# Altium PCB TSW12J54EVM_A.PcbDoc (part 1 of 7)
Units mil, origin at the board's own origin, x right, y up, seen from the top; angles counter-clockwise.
Board outline 6301 x 2680 mil, 10 copper layers (Top Layer - L1, Gnd-Plane - L2, Signals - L3, Gnd-Plane - L4, Pwr Plane - L5, Signals - L6, Gnd-Plane - L7, Signals - L8, Gnd-Plane - L9, Bottom Layer - L10), stack 57.8 mil thick; 650 components, 374 nets, 2074 pads, 1402 vias.
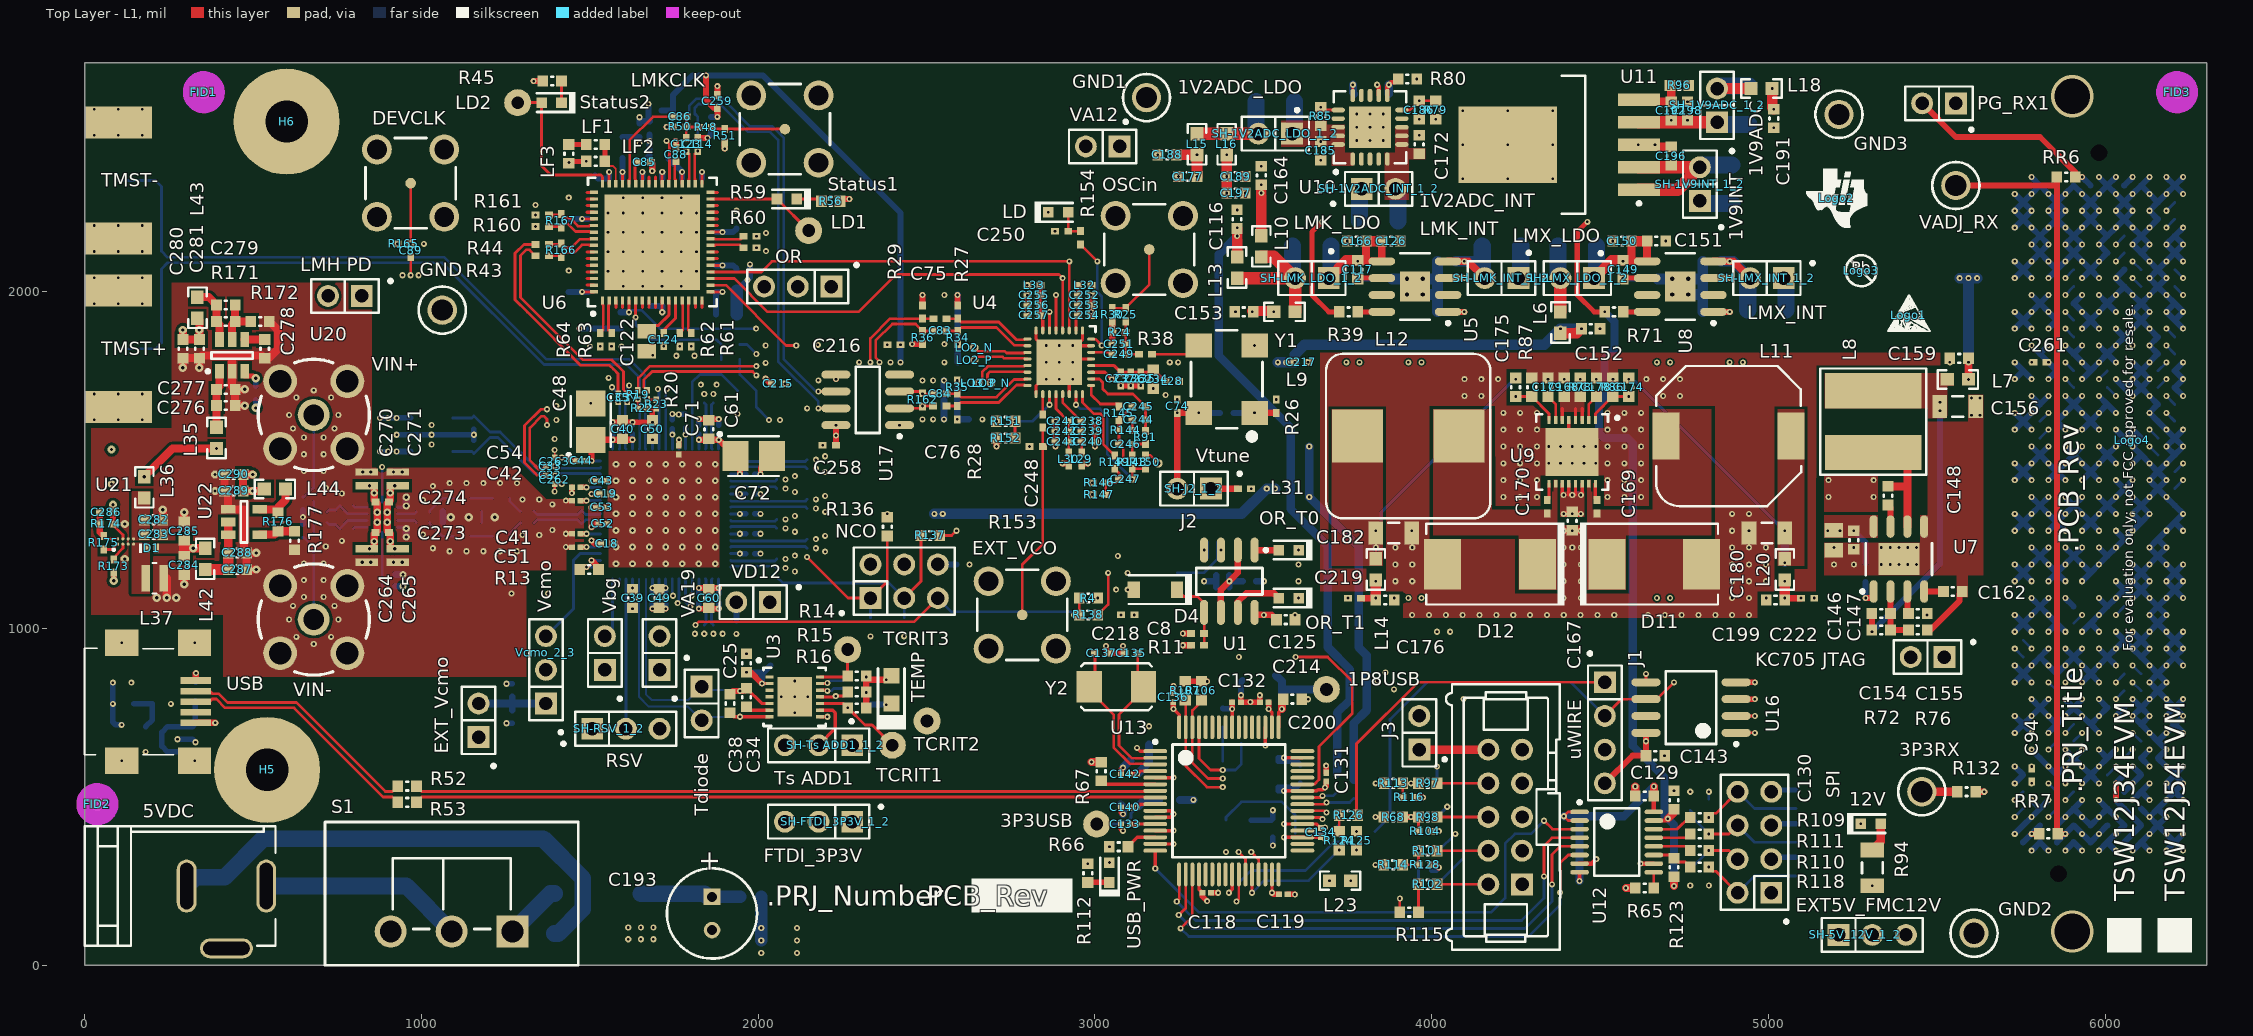
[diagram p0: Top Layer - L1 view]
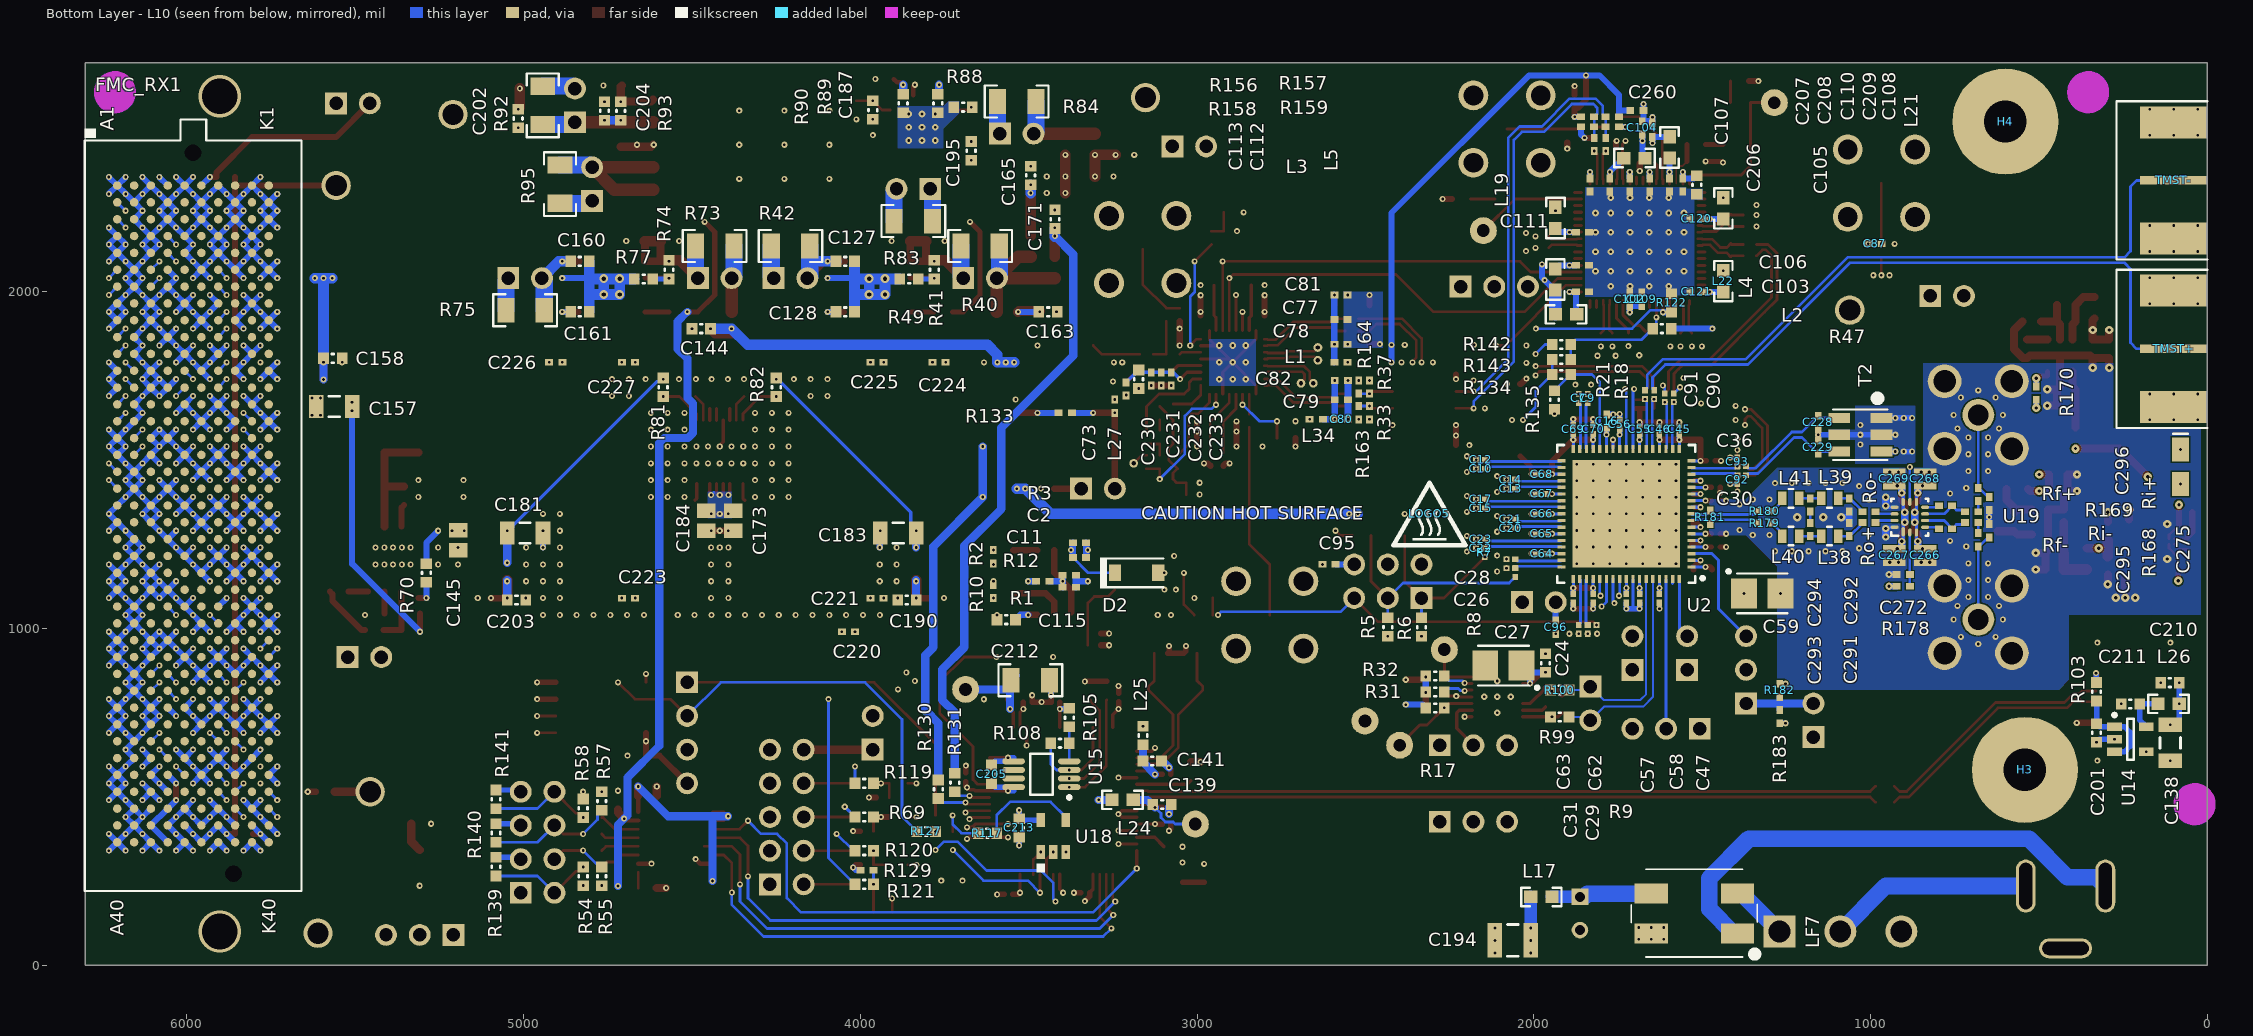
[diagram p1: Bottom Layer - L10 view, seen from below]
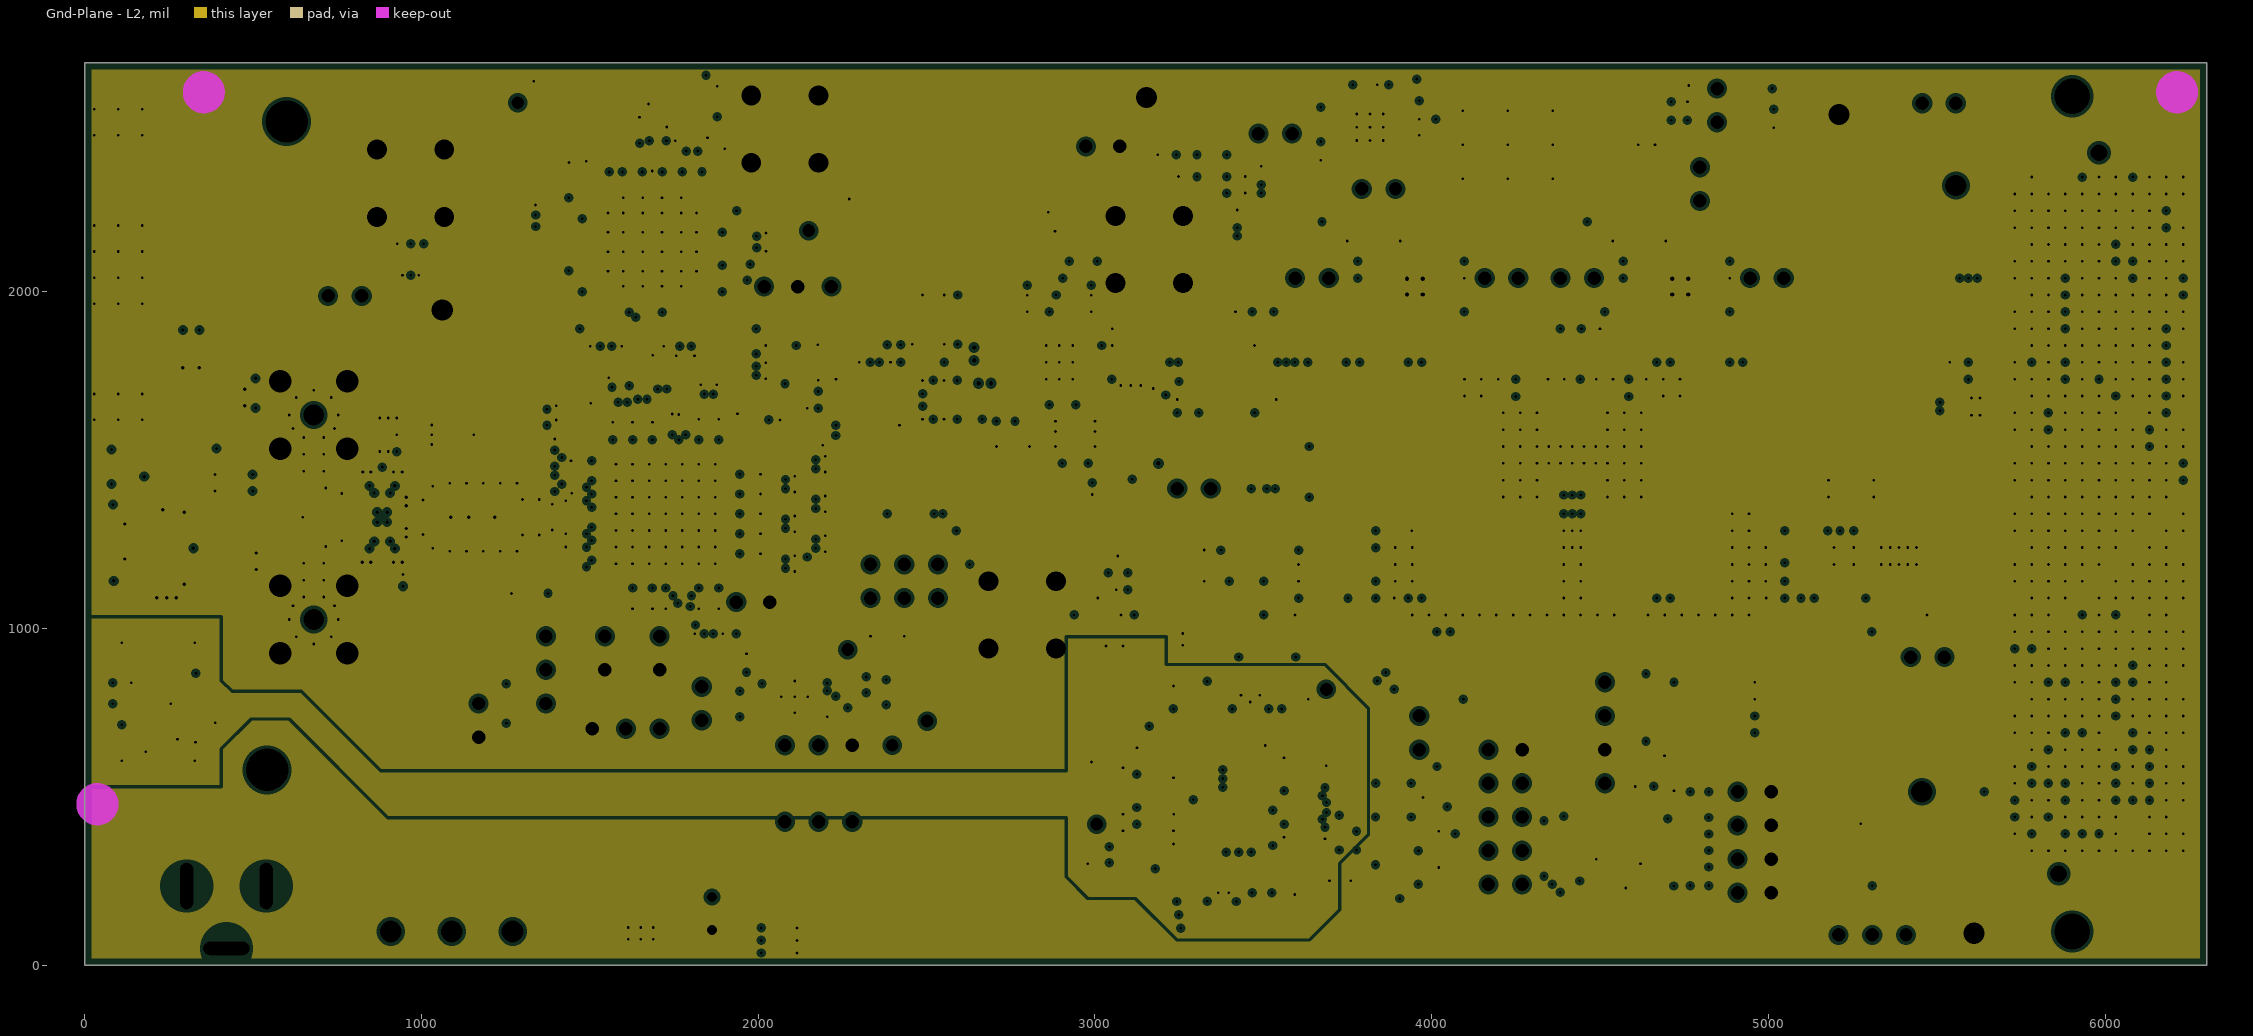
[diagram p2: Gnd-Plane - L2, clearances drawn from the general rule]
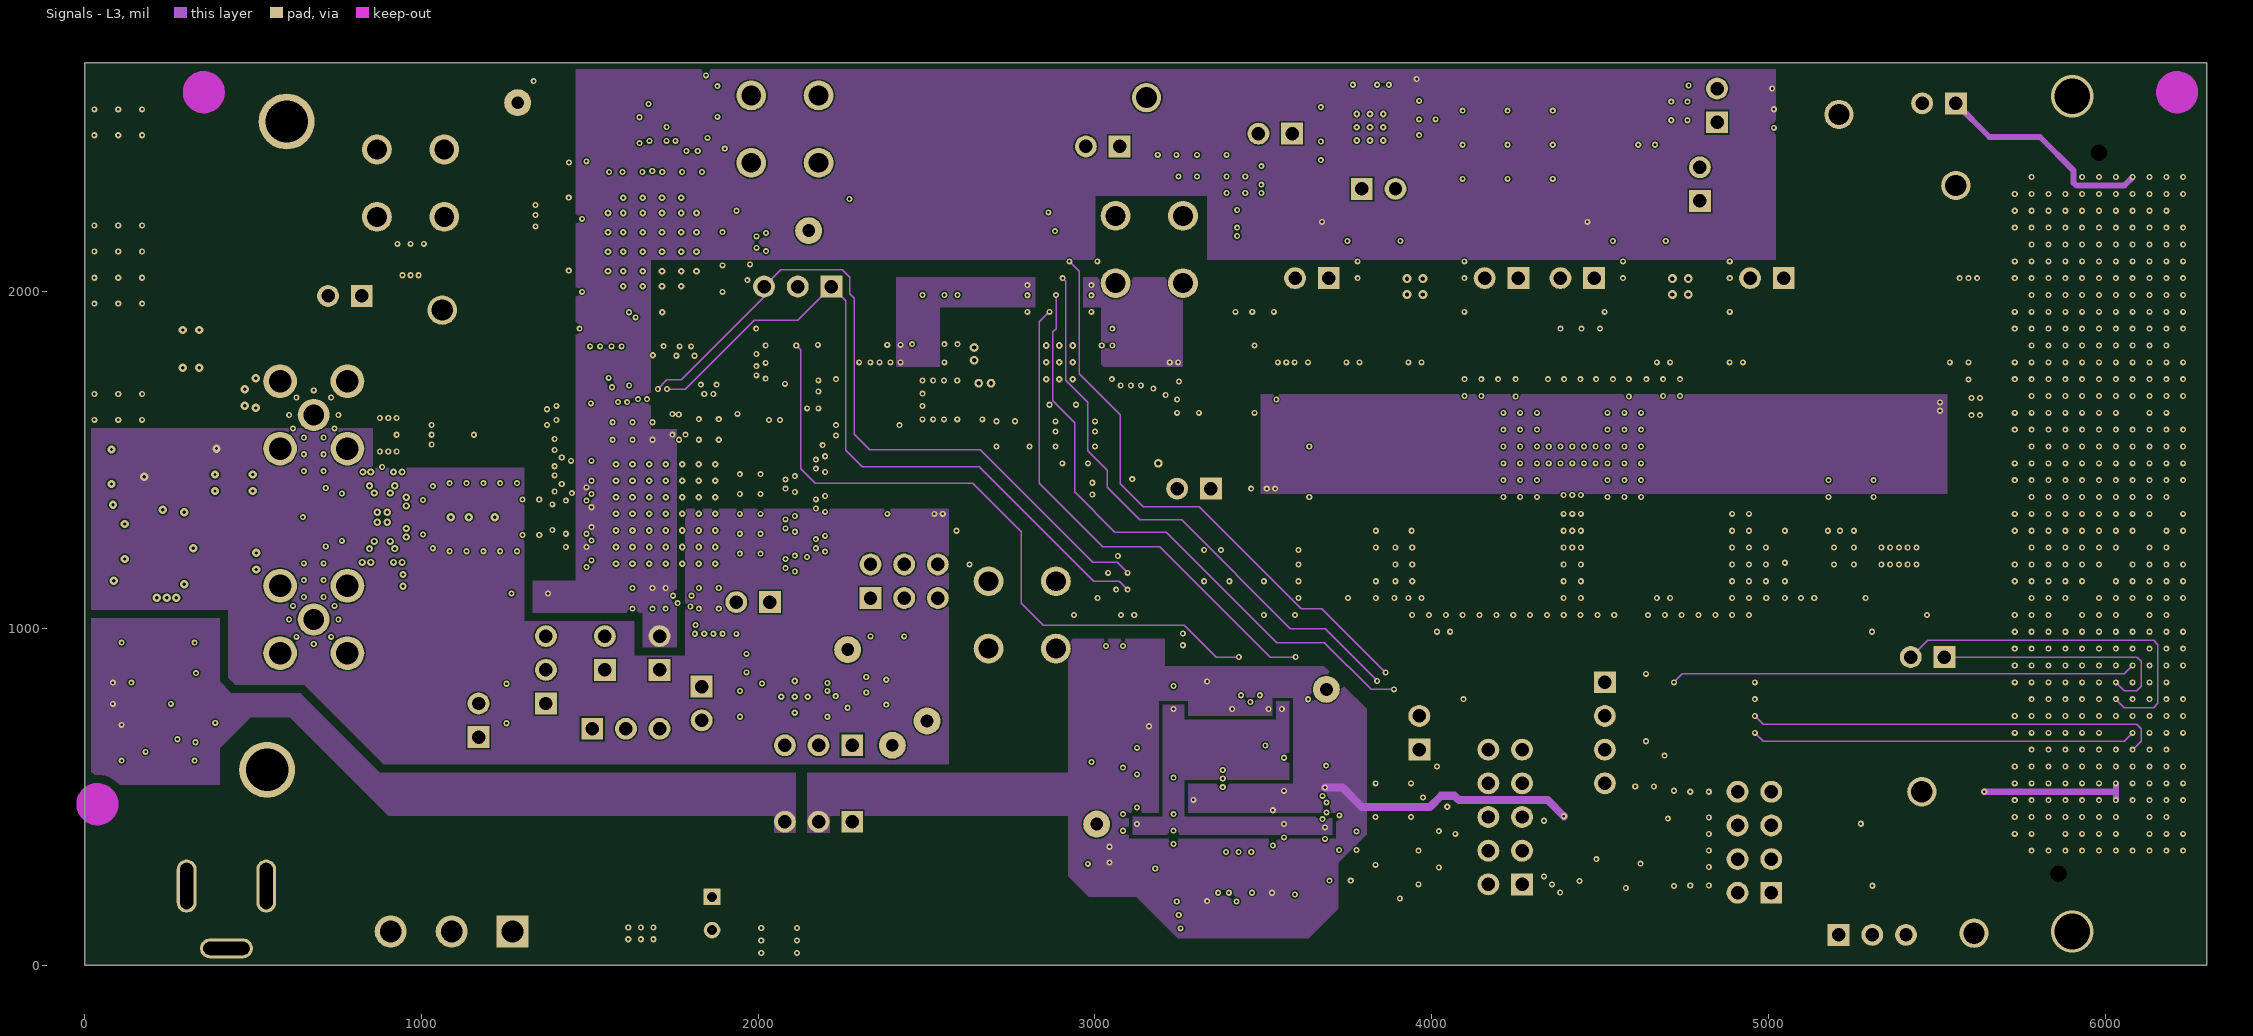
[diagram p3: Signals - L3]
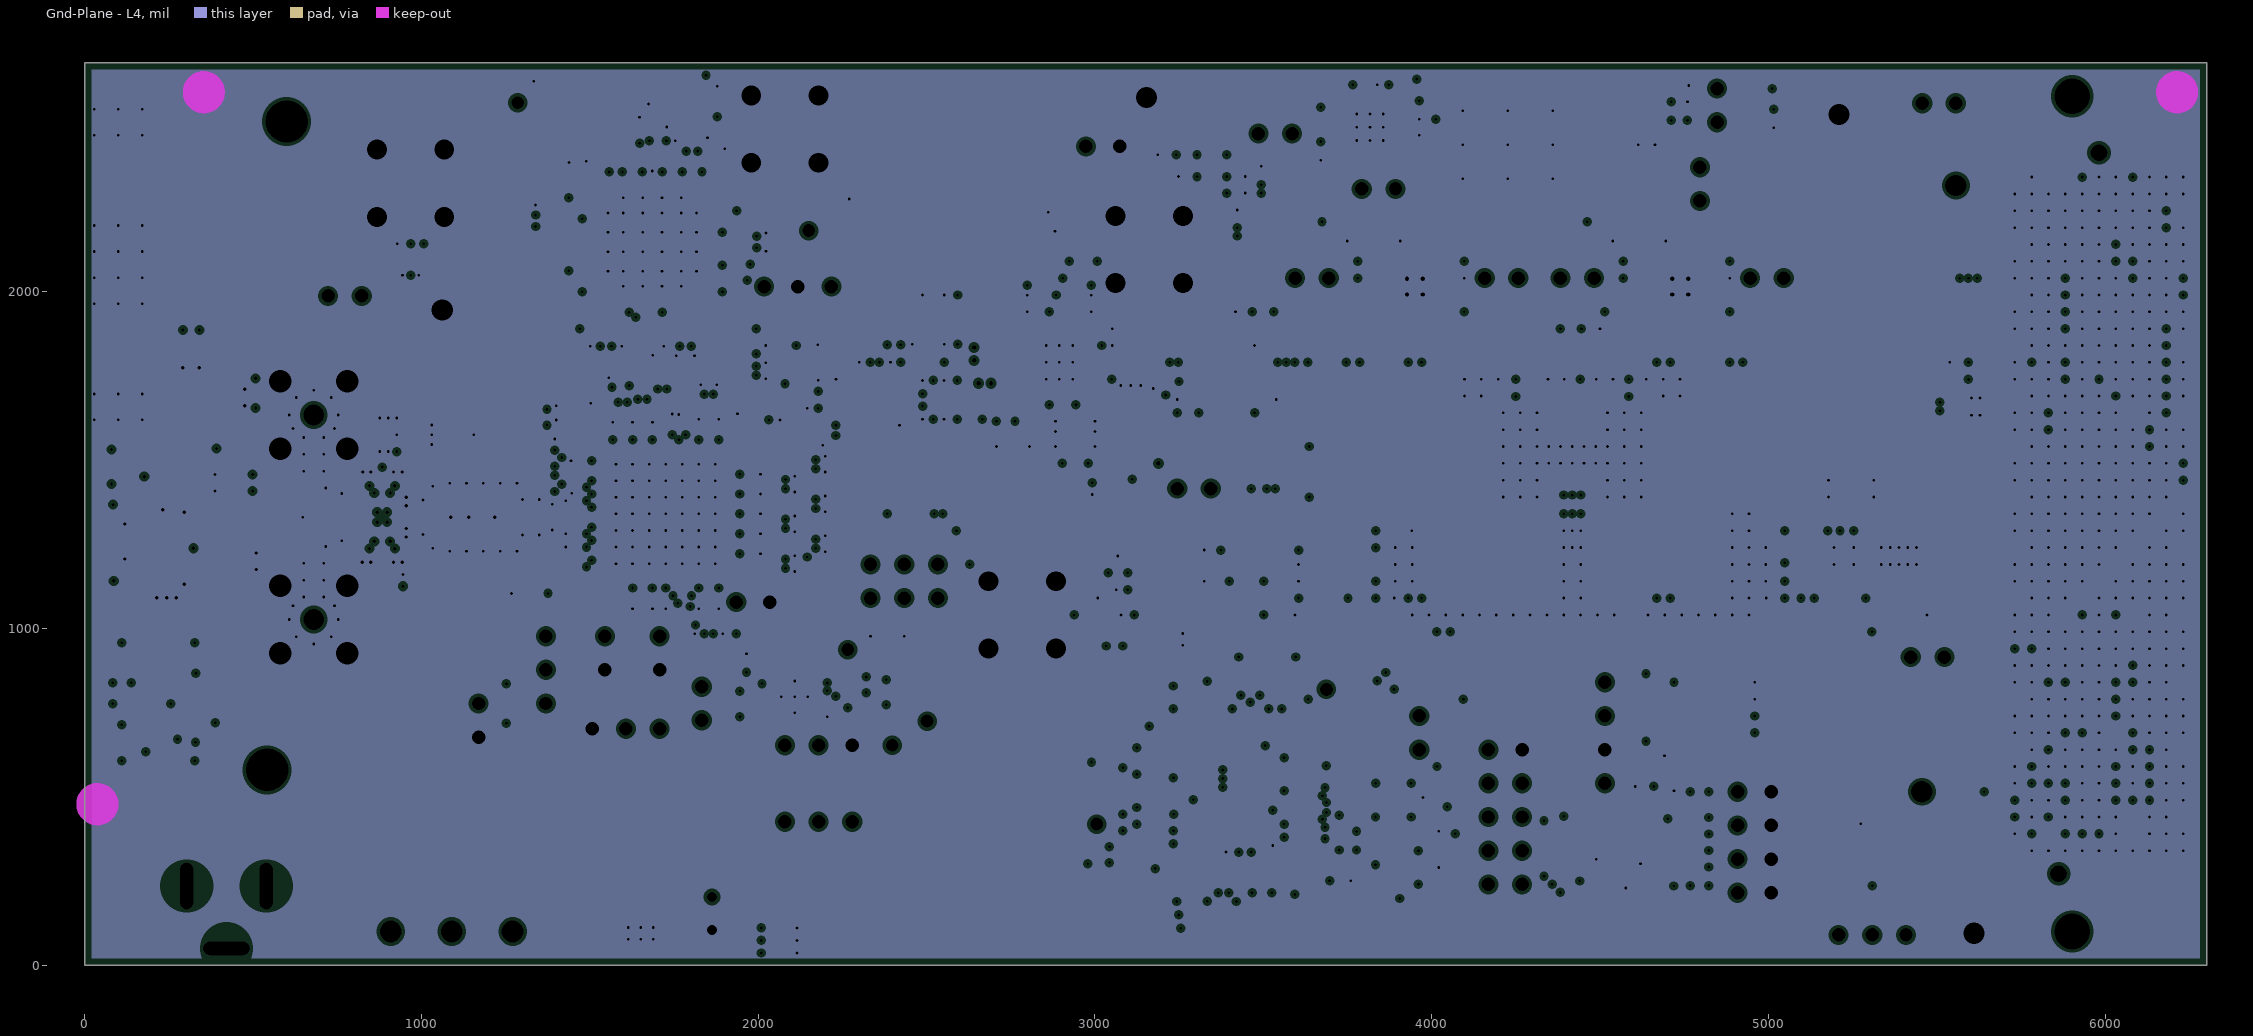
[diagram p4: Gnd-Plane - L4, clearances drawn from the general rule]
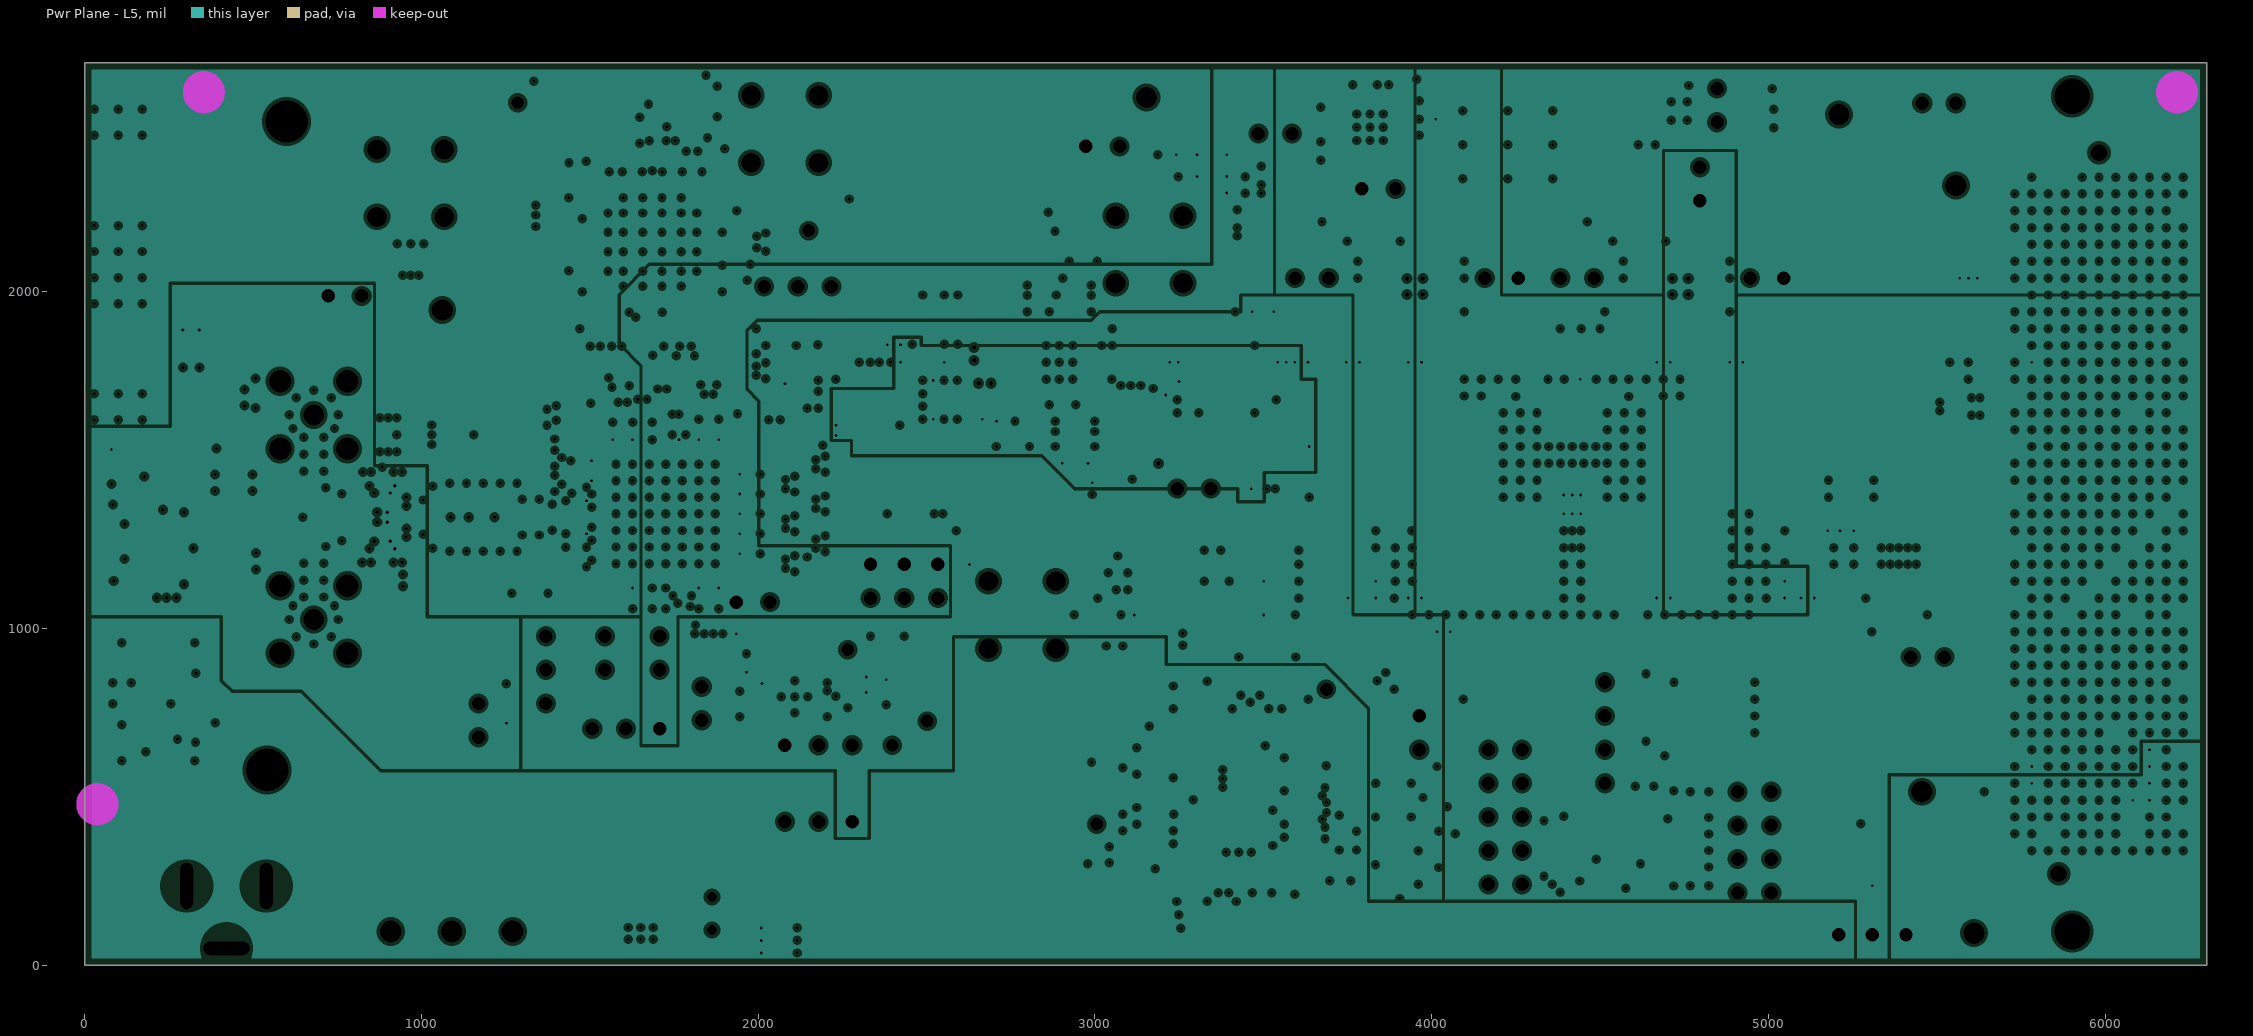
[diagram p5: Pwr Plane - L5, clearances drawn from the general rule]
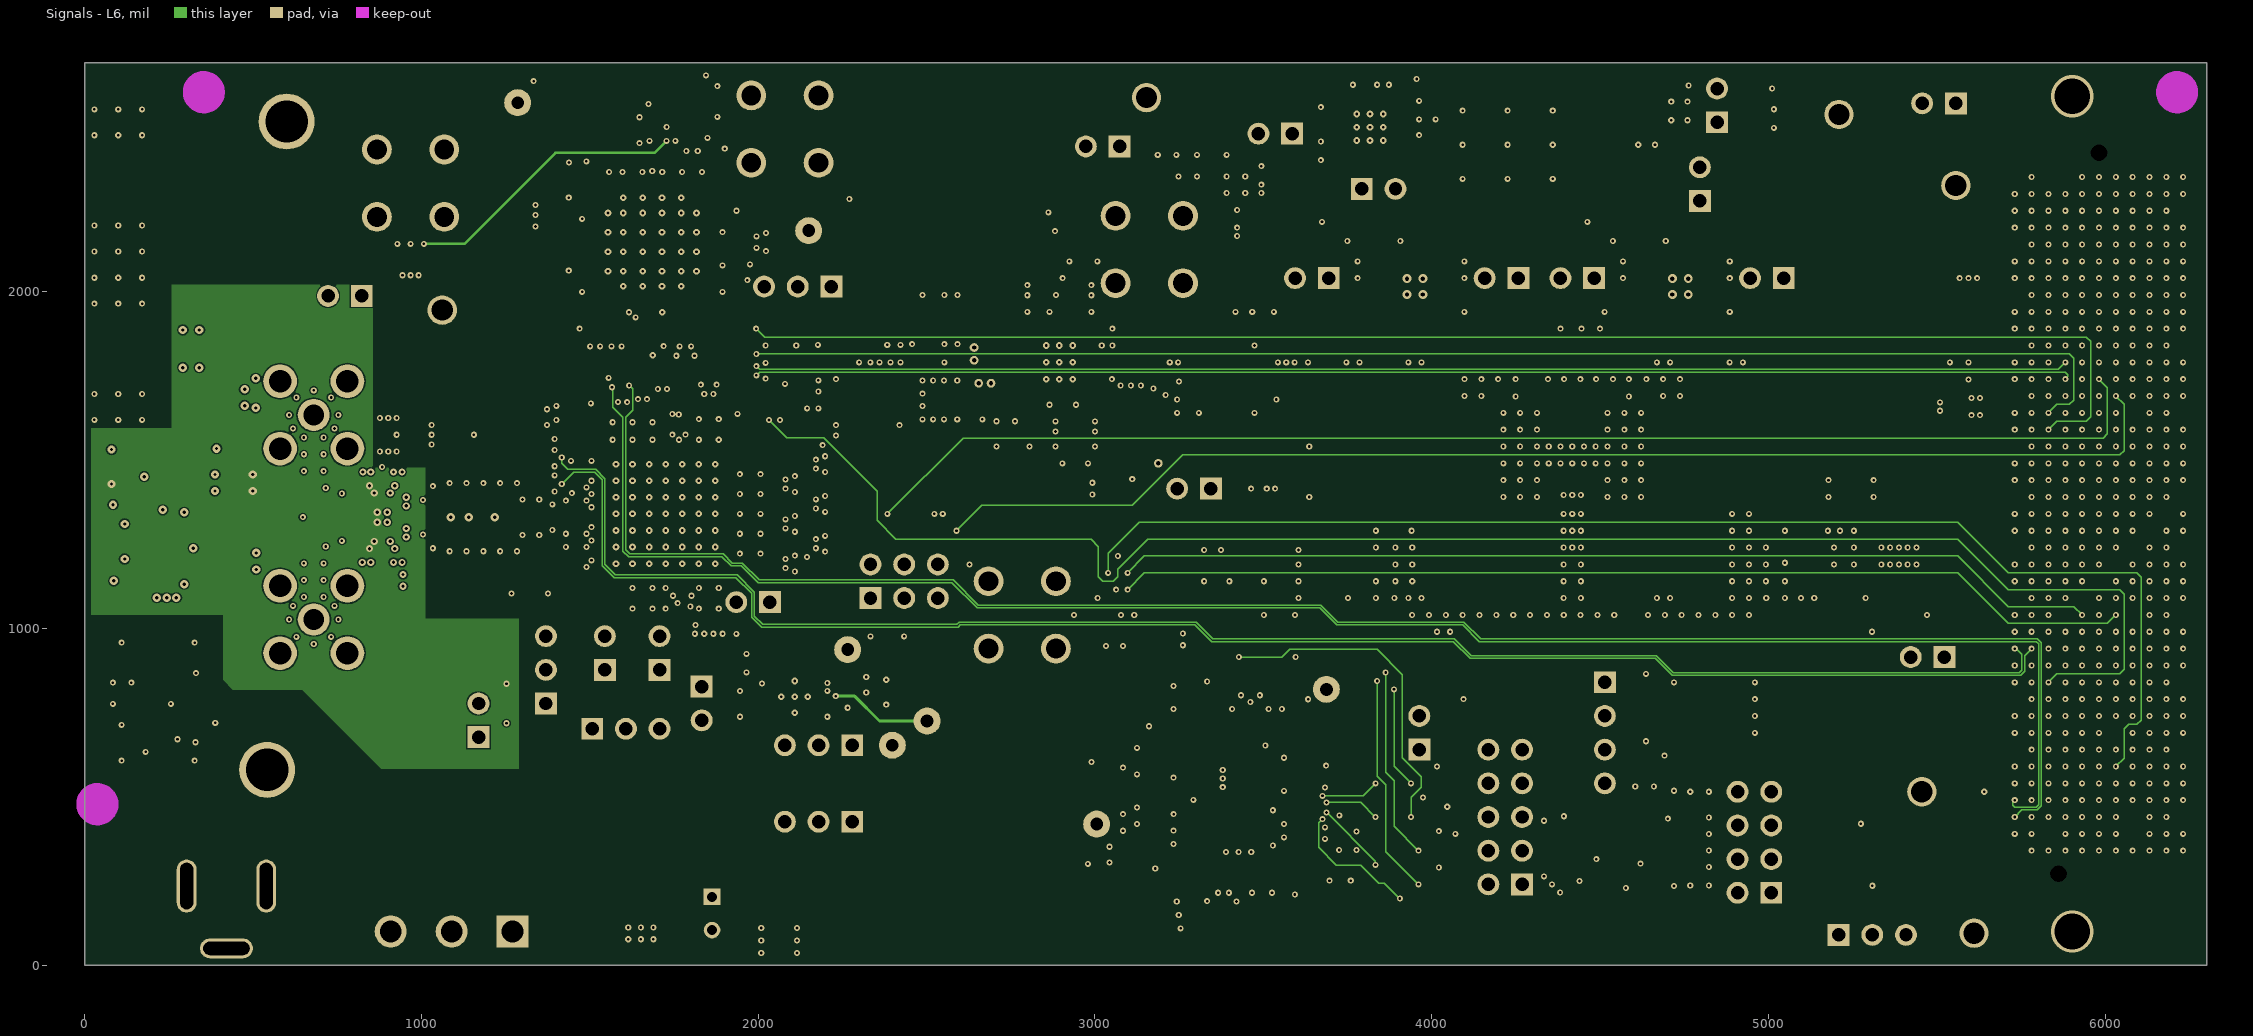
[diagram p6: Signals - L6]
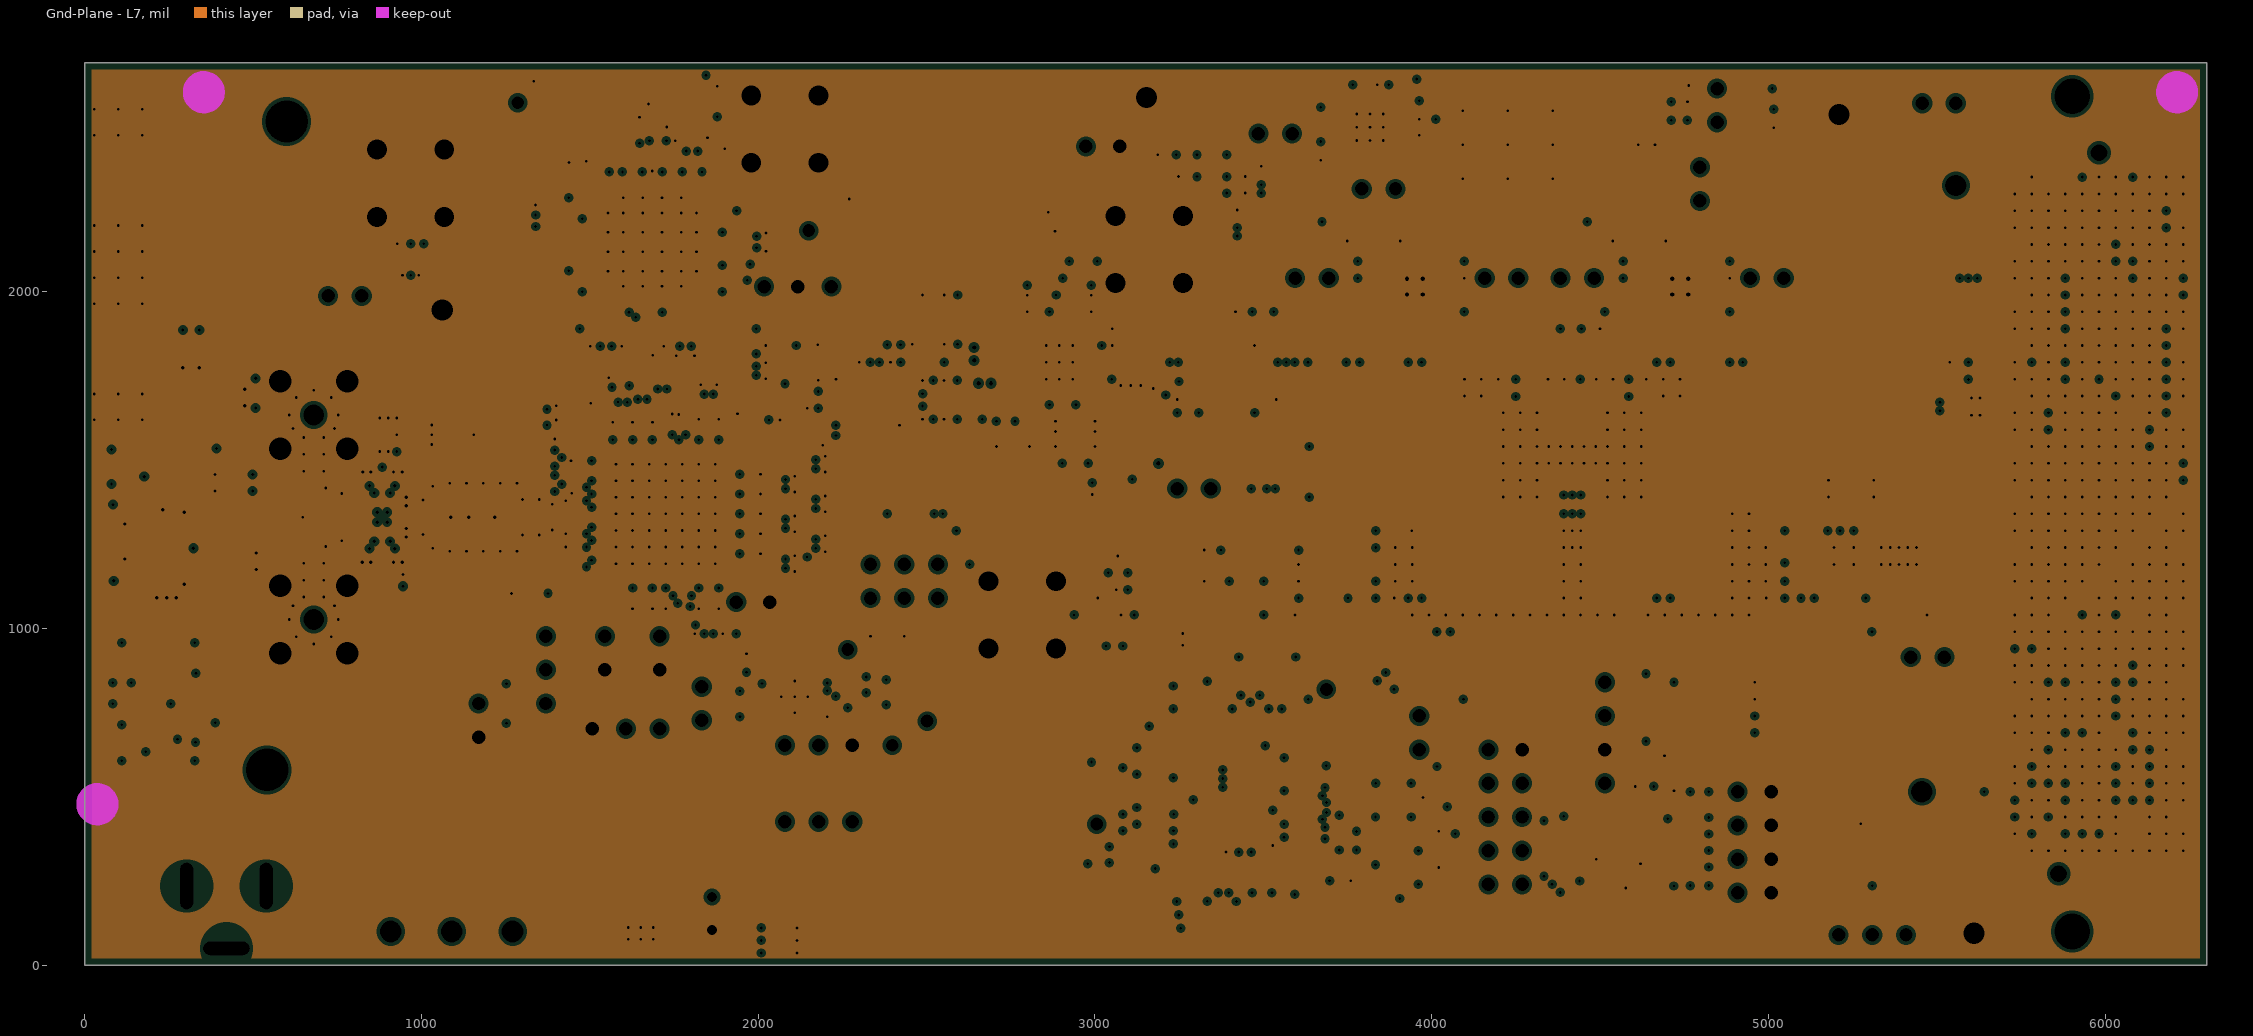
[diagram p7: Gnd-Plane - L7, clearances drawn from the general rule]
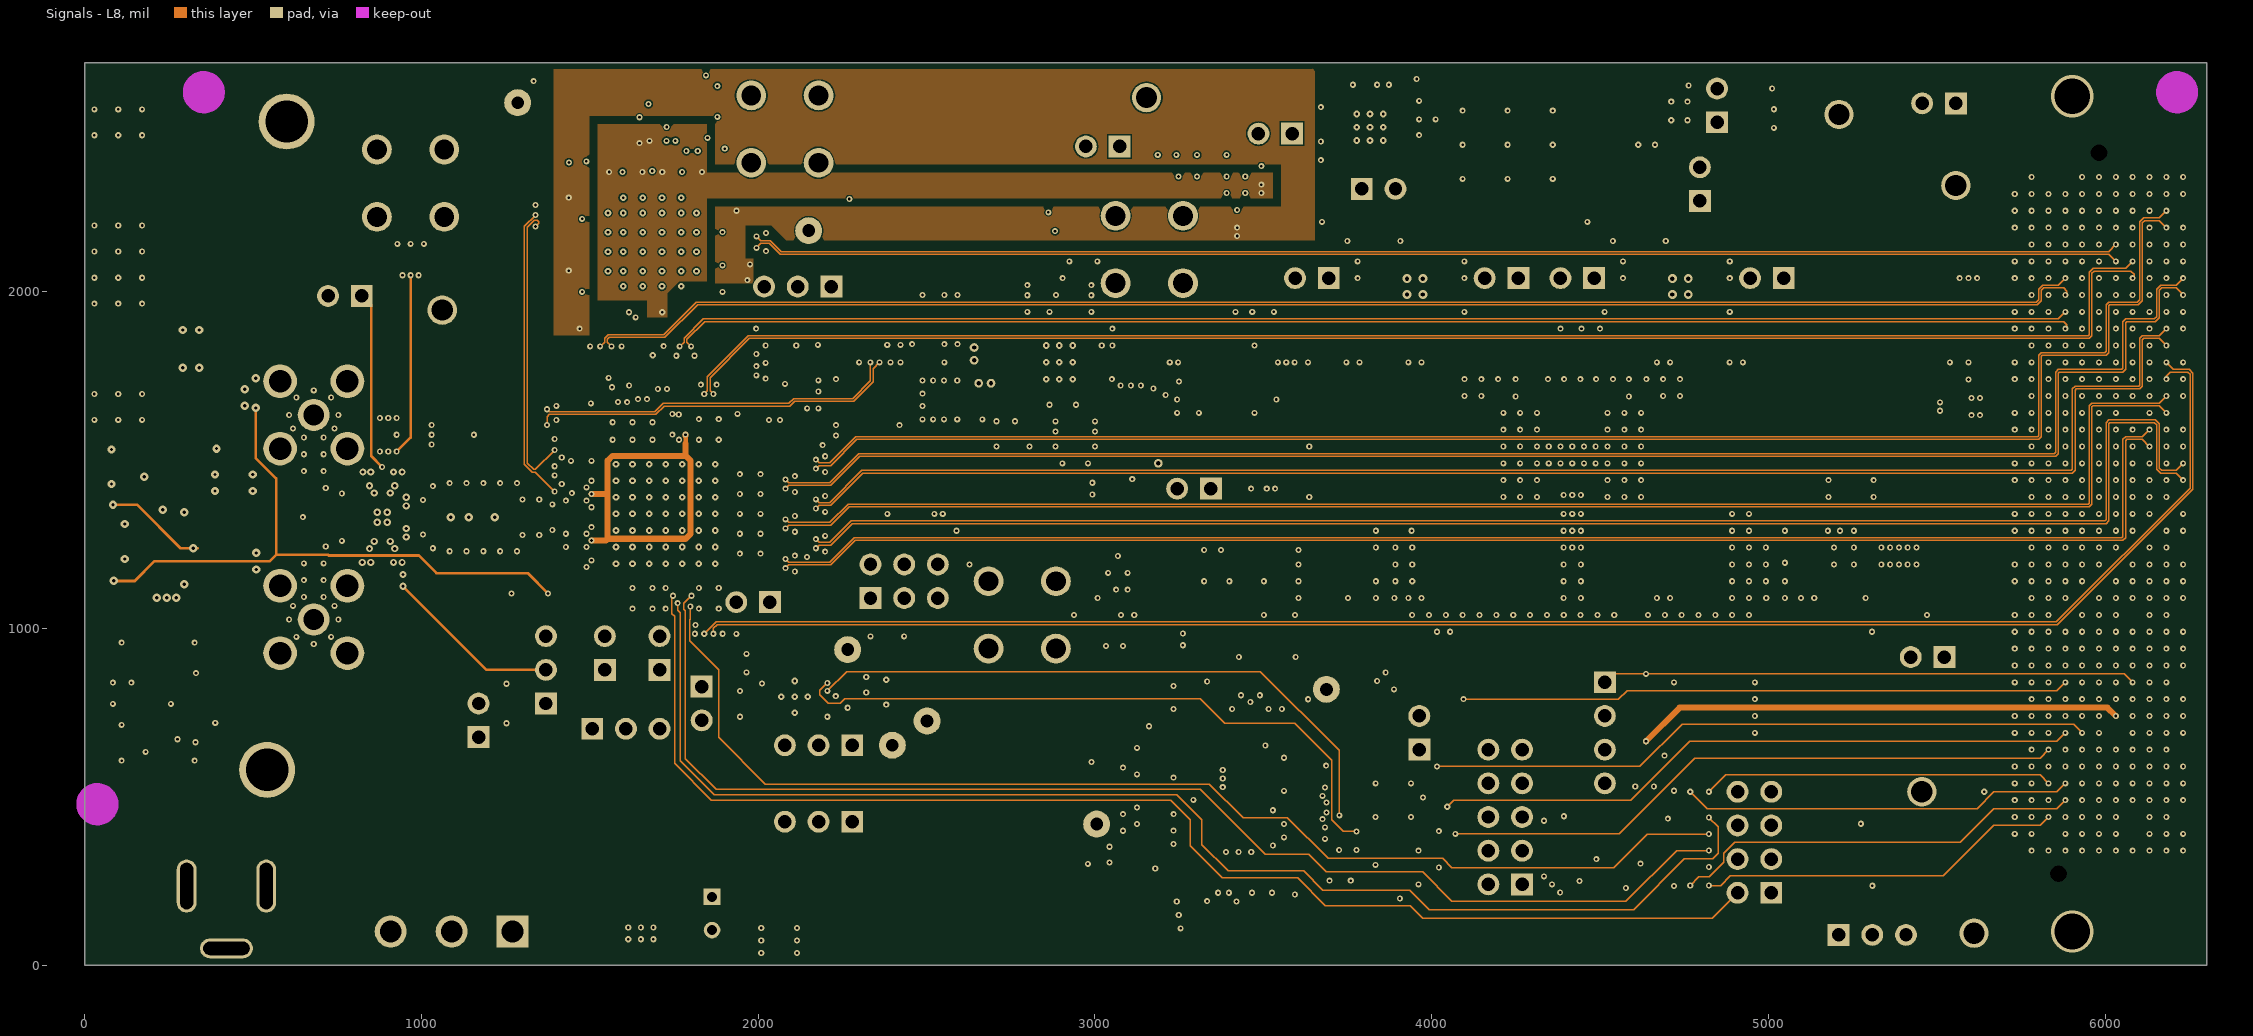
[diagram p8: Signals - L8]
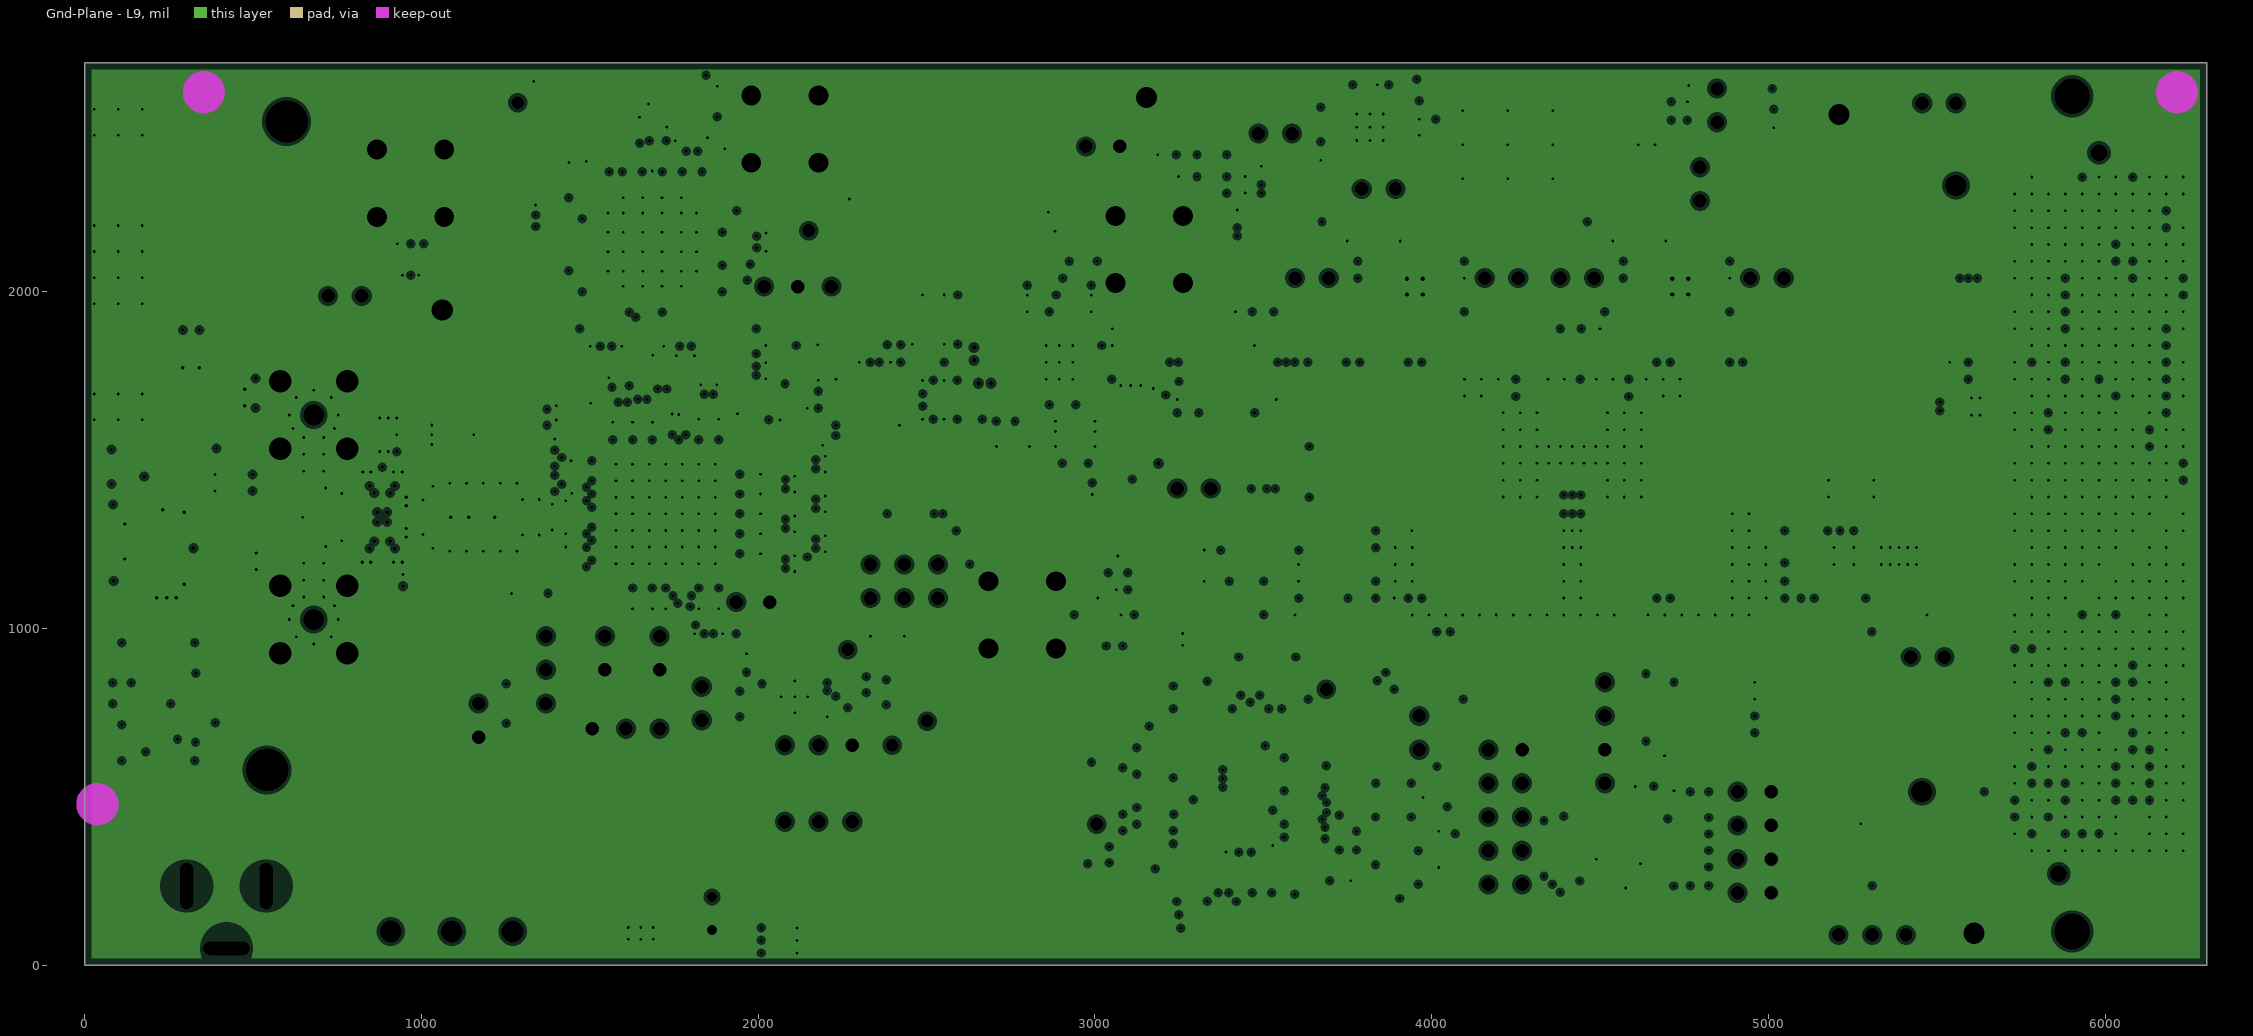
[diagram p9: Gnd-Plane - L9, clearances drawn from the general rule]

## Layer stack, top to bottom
Top Solder: solder mask 0.4, Solder Resist, Dk 3.5
Top Layer - L1: signal copper 0.6
Dielectric1: core 4, Rogers RO4350, Dk 3.66
Gnd-Plane - L2: plane copper 1.2, net (Multiple Nets)
Dielectric8: prepreg 6.7, NP 4000-6, Dk 4.11
Signals - L3: signal copper 0.6
Dielectric2: core 6, NP 4000-6, Dk 4.11
Gnd-Plane - L4: plane copper 1.2, net GND
Dielectric7: prepreg 4.1, NP 4000-6, Dk 4.11
Pwr Plane - L5: plane copper 1.2, net (Multiple Nets)
Dielectric9: core 6, NP 4000-6, Dk 4.11
Signals - L6: signal copper 0.6
Dielectric3: prepreg 6.7, NP 4000-6, Dk 4.11
Gnd-Plane - L7: plane copper 1.2, net GND
Dielectric6: core 4, Rogers RO4350, Dk 3.66
Signals - L8: signal copper 0.6
Dielectric4: prepreg 7.3, Rogers RO4350, Dk 3.66
Gnd-Plane - L9: plane copper 1.2, net GND
Dielectric5: core 4, Rogers RO4350, Dk 3.66
Bottom Layer - L10: signal copper 0.6
Bottom Solder: solder mask 0.4, Solder Resist, Dk 3.5

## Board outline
0,0 6301,0 6301,2680 0,2680

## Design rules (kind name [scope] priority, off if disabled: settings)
AcuteAngle [All] p1: minimum=4.50000000000000E+0001 checktracksonly=FALSE
AssemblyTestPointUsage [All] p1: valid=2
Clearance Clearance_6 [InNamedPolygon('Top Layer - L1 - Anolog In GNF')] p1: gap=8
Clearance Clearance_5 [InNamedPolygon('Top Layer - L1 - Anolog In GNF')] p2: gap=10
Clearance Clearance_4 [InNamedPolygon('Top Layer - L1 - Anolog In GNF')] p3: gap=16
Clearance Clearance_3 [InNamedPolygon('Bottom Layer - L10 - Anolog In GNF')] p4: gap=16
Clearance Clearance_2 [InNamedPolygon('Bottom Layer - L10 - Anolog In GNF')] p5: gap=10
Clearance Clearance_1 [InNamedPolygon('Bottom Layer - L10 - Anolog In GNF')] p6: gap=24
Clearance "0201 PADS" [HasFootprint('0201') vs HasFootprint('0201')] p7: gap=7.87
Clearance Clearance_BoardEdge_MountingHoles [OnCopper and InComponentClass('Mounting Holes') vs IsKeepOut] p8: gap=40
Clearance Clearance_BoardEdge_Poly [OnCopper and InPoly vs IsKeepOut] p9: gap=25
Clearance Clearance_BoardEdge [OnCopper and Not InComponentClass('Logo') and not InComponentClass('FiducialMark') and not InRegion(000,000,6301,2680) and Not IsKeepout vs IsKeepOut] p10: gap=25
Clearance [All] p11: gap=4
ComponentClearance ComponentClearance_2 [(HasFootprint('NY PMS 440 0025 PH'))] p1: gap=5 collisioncheckmode=3 verticalgap=10 showdistances=FALSE
ComponentClearance ComponentClearance_1 [HasFootprint('TESTPOINT')] p2: gap=3.5 collisioncheckmode=3 verticalgap=10 showdistances=FALSE
ComponentClearance ComponentClearance_Shared_Pad [(InComponent('R7') OR InComponent('R8') OR InComponent('R9') OR InComponent('C22') OR InComponent('C26') OR InComponent('C29') OR InComponent('SH-*') OR InComponent('RSV*') OR InComponent('Ts ADD1*') OR InComponent('LMX_INT*') OR InComponent('LMX_LDO*') OR InComponent('LMK_INT*') OR InComponent('LMK_LDO*') OR InComponent('1V2ADC_INT*') OR InComponent('1V2ADC_LDO*') OR InComponent('1V9INT*') OR InComponent('1V9ADC*') OR InComponent('+12V*') OR InComponent('C32*') OR InComponent('C262*')OR InComponent('C33*') OR InComponent('C263*') OR InComponent('C92*') OR InComponent('C93*') OR InComponent('C89*') OR InComponent('R165*') OR InComponent('Vcmo_2_3*') OR InComponent('Vcmo*'))] p3: gap=0 collisioncheckmode=3 verticalgap=0 showdistances=FALSE
ComponentClearance ComponentClearance_0201 [HasFootprint('0201*') or HasFootprint('LQA68A') vs HasFootprint('0201*') or HasFootprint('LQA68A')] p4: gap=10 collisioncheckmode=3 verticalgap=10 showdistances=FALSE
ComponentClearance ComponentClearance_ScrewToNut [(HasFootprint('NY PMS 440 0025 PH')) vs (HasFootprint('Keystone_1902C'))] p5: gap=5 collisioncheckmode=3 verticalgap=10 showdistances=FALSE
ComponentClearance ComponentClearance_MountingHoles [InComponentClass('Mounting Holes')] p6: gap=250 collisioncheckmode=3 verticalgap=100000 showdistances=FALSE
ComponentClearance ComponentClearance_SmallPassives [HasFootprint('0201*') or HasFootprint('0402*') or HasFootprint('0508') or HasFootprint('0603*') or HasFootprint('0612') or HasFootprint('0805*') or HasFootprint('0815*') or HasFootprint('0830*') or HasFootprint('1206*') or HasFootprint('1210*') or HasFootprint('1808*') or HasFootprint('1812*') or HasFootprint('1825*') or HasFootprint('2010*') or HasFootprint('2220*') or HasFootprint('2225*') or HasFootprint('2512*') or HasFootprint('2728*') or HasFootprint('3518*') or HasFootprint('LQA68A*')  or HasFootprint('RTV0032A*') or HasFootprint('DBV0005A*') or HasFootprint('XTAL_ABM3*') or HasFootprint('RGW0020A*') or HasFootprint('M08A*') or HasFootprint('LED_LTST-C190*') or HasFootprint('DDA0008B*') or HasFootprint('SOIJ-SM8*') or HasFootprint('MSOP-MS8*') or HasFootprint('SDA16A*') or HasFootprint('OSC_CWX*') or HasFootprint('3528-21*') or HasFootprint('PW0016A*') or HasFootprint('MRA08A*') or HasFootprint('TJ5A*') or HasFootprint('SOD-123*') or HasFootprint('RLY0068A*') or HasFootprint('SOP-5_.95MM_(DBV)*') or HasFootprint('IND_2.0X2.0MM_A*') or HasFootprint('SOD-882*') or HasFootprint('YFX0008ADAC*') vs HasFootprint('0201*') or HasFootprint('0402*') or HasFootprint('0508') or HasFootprint('0603*') or HasFootprint('0612') or HasFootprint('0805*') or HasFootprint('0815*') or HasFootprint('0830*') or HasFootprint('1206*') or HasFootprint('1210*') or HasFootprint('1808*') or HasFootprint('1812*') or HasFootprint('1825*') or HasFootprint('2010*') or HasFootprint('2220*') or HasFootprint('2225*') or HasFootprint('2512*') or HasFootprint('2728*') or HasFootprint('3518*') or HasFootprint('LQA68A*')  or HasFootprint('RTV0032A*') or HasFootprint('DBV0005A*') or HasFootprint('XTAL_ABM3*') or HasFootprint('RGW0020A*') or HasFootprint('M08A*') or HasFootprint('LED_LTST-C190*') or HasFootprint('DDA0008B*') or HasFootprint('SOIJ-SM8*') or HasFootprint('MSOP-MS8*') or HasFootprint('SDA16A*') or HasFootprint('OSC_CWX*') or HasFootprint('3528-21*') or HasFootprint('PW0016A*') or HasFootprint('MRA08A*') or HasFootprint('TJ5A*') or HasFootprint('SOD-123*') or HasFootprint('RLY0068A*') or HasFootprint('SOP-5_.95MM_(DBV)*') or HasFootprint('IND_2.0X2.0MM_A*') or HasFootprint('SOD-882*') or HasFootprint('YFX0008ADAC*')] p7: gap=5 collisioncheckmode=3 verticalgap=5 showdistances=FALSE
ComponentClearance ComponentClearance_THtoSMT [IsThruComponent vs IsSMTComponent] p8: gap=10 collisioncheckmode=3 verticalgap=0 showdistances=FALSE
ComponentClearance ComponentClearance_THtoTH [IsThruComponent vs IsThruComponent] p9: gap=10 collisioncheckmode=3 verticalgap=100000 showdistances=FALSE
ComponentClearance [All] p10: gap=10 collisioncheckmode=3 verticalgap=10 showdistances=FALSE
DiffPairsRouting [All] p1: maxlimit=100 minlimit=4 mostfreqgap=4 toplayer_mingap=8 toplayer_prefgap=8 toplayer_minwidth=15 toplayer_maxwidth=15 toplayer_prefwidth=15 midlayer1_minwidth=15 midlayer1_maxwidth=15 midlayer1_prefwidth=15 midlayer2_minwidth=15 midlayer2_maxwidth=15 midlayer2_prefwidth=15 midlayer3_minwidth=15 midlayer3_maxwidth=15 midlayer3_prefwidth=15 bottomlayer_mingap=8 bottomlayer_prefgap=8 bottomlayer_minwidth=15 bottomlayer_maxwidth=15 bottomlayer_prefwidth=15 maxuncoupledlength=1000
FabricationTestPointUsage TestPointUsage [All] p1: valid=2 allowmultiple=FALSE
FabricationTestpoint Testpoint [All] p1: side=3 testpointundercomponent=TRUE minsize=40 maxsize=100 preferedsize=60 minholesize=0 maxholesize=40 preferedholesize=32 testpointgrid=1 allowsidetop=TRUE allowsidebottom=TRUE usegrid=TRUE gridtolerance=0.01
FanoutControl Fanout_LCC [IsLCC] p1: bgadir=Out bgaviamode=Centered fanoutstyle=Auto fanoutdirection=Alternating viagrid=1 // Fanout_LCC (Default Rule)
FanoutControl Fanout_BGA [IsBGA] p2: bgadir=Out bgaviamode=Centered fanoutstyle=Auto fanoutdirection=Alternating viagrid=1 // Fanout_BGA (Default Rule)
FanoutControl Fanout_Default [All] p4: bgadir=Out bgaviamode=Centered fanoutstyle=Auto fanoutdirection=Alternating viagrid=1 // Fanout_Default (Default Rule)
FanoutControl Fanout_Small [(CompPinCount < 5)] p5: bgadir=Out bgaviamode=Centered fanoutstyle=Auto fanoutdirection=OutThenIn viagrid=1 // Fanout_Small (Default Rule)
HoleSize [All] p1: absolutevalues=TRUE maxlimit=251 minlimit=7.87 maxpercent=80.000 minpercent=20.000
MinimumAnnularRing [All] p1: minimumring=5
MinimumSolderMaskSliver MinimumSolderMaskSliver_U21 [All vs InComponent('U21')] p1: minsoldermaskwidth=3.74
MinimumSolderMaskSliver MinimumSolderMaskSliver_U19 [InComponent('U19')] p2: minsoldermaskwidth=3.5
MinimumSolderMaskSliver MinimumSolderMaskSliver_Logo [InComponentClass('Logo') vs InComponentClass('Logo')] p3: minsoldermaskwidth=0.7
MinimumSolderMaskSliver [All] p4: minsoldermaskwidth=4
NetAntennae "NetAntennae U2 or U6" [(InNet('U2-*') OR InNet('U6-*'))] p1: netantennaetolerance=50
NetAntennae [All] p2: netantennaetolerance=0
PlaneClearance [All] p1: clearance=10
PlaneConnect [All] p1: planeconnectstyle=Direct reliefexpansion=10 reliefentries=4 reliefconductorwidth=10 reliefairgap=10
PolygonConnect [All] p1: connectstyle=Direct reliefconductorwidth=10 reliefentries=4 polygonreliefangle="90 Angle" airgapwidth=10
RoutingVias [All] p1: holewidth=16 width=34 viastyle="Through Hole" minholewidth=7.87 minwidth=18 maxholewidth=106 maxwidth=126
SMDToCorner [All] p1: distance=30000
SilkToSilkClearance SilkToSilkClearance_Pb-FreeLogo [(HasFootprint('Pb-Free_Overlay_Medium') OR HasFootprint('Pb-Free_Overlay_Small')) vs (HasFootprint('Pb-Free_Overlay_Medium') OR HasFootprint('Pb-Free_Overlay_Small'))] p1: silktosilkclearance=0
SilkToSilkClearance [All] p2: silktosilkclearance=5
SilkToSolderMaskClearance SilkscreenOverComponentPads [IsPad] p1: minsilkscreentomaskgap=5 clearancetoexposedcopper=TRUE
SolderMaskExpansion [All] p1: expansion=3
UnpouredPolygon [All] p1: allowunpoured=FALSE
Width [All] p1: maxlimit=100 minlimit=4 preferedwidth=10 checkconnectedcopper=TRUE
13 further rules are at their usual default settings.

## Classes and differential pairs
component class AssemblyNote: !PCB H9 H10 H11 H12 ZZ1 ZZ2 ZZ3 ZZ4
component class Header: 1V2ADC_INT 1V2ADC_LDO 1V9ADC 1V9INT EXT5V_FMC12V EXT_Vcmo FTDI_3P3V J1 J2 J3 "KC705 JTAG" "LMH PD" LMK_INT LMK_LDO LMX_INT LMX_LDO NCO OR PG_RX1 RSV SPI Tdiode "Ts ADD1" VA12 VA19 Vbg Vcmo VD12
component class Shunt: SH-1V2ADC_INT_1_2 SH-1V2ADC_LDO_1_2 SH-1V9ADC_1_2 SH-1V9INT_1_2 SH-5V_12V_1_2 SH-FTDI_3P3V_1_2 SH-J2_1_2 SH-LMK_INT_1_2 SH-LMK_LDO_1_2 SH-LMX_INT_1_2 SH-LMX_LDO_1_2 SH-RSV_1_2 "SH-Ts ADD1_1_2" Vcmo_2_3
component class 0402L: C272
component class FiducialMark: FID1 FID2 FID3
component class Logo: Logo2
component class "Mounting Holes": H5 H6
differential pair DEV_CLK: +DEV_CLK_P -DEV_CLK_N
differential pair CLK10: +CLK10_P -CLK10_N
differential pair TMST: +TMST_P -TMST_N
differential pair CLK3: +CLK3_P -CLK3_N
differential pair CLK11: +CLK11_P -CLK11_N
differential pair CLK0: +CLK0_P -CLK0_N
differential pair CLK4: +CLK4_P -CLK4_N
differential pair CLKIN1: +CLKIN1_P -CLKIN1_N
differential pair D0: +D0_P -D0_N
differential pair D1: +D1_P -D1_N
differential pair D2: +D2_P -D2_N
differential pair D3: +D3_P -D3_N
differential pair D4: +D4_P -D4_N
differential pair D5: +D5_P -D5_N
differential pair D6: +D6_P -D6_N
differential pair D7: +D7_P -D7_N
differential pair DEVCLKARX: +DEVCLKARX_P -DEVCLKARX_N
differential pair DEVCLKBRX: +DEVCLKBRX_P -DEVCLKBRX_N
differential pair DEVCLK: +DEVCLK_P -DEVCLK_N
differential pair SYNC: +SYNC_P -SYNC_N
differential pair SYSREFRX: +SYSREFRX_P -SYSREFRX_N
differential pair SYSREFTX: +SYSREFTX_P -SYSREFTX_N
differential pair SYSRF: +SYSRF_P -SYSRF_N
differential pair VIN: +VIN_P -VIN_N
differential pair SYNC~/TMST: +SYNC~/TMST_P -SYNC~/TMST_N
differential pair LO1: +LO1_P -LO1_N
differential pair LO2: +LO2_P -LO2_N
differential pair LO3: +LO3_P -LO3_N
differential pair LO4: +LO4_P -LO4_N
differential pair TRF_OUTA: +TRF_OUTA_P -TRF_OUTA_N
differential pair TRF_OUTB: +TRF_OUTB_P -TRF_OUTB_N
differential pair FMC_SYSREF: +FMC_SYSREF_P -FMC_SYSREF_N
differential pair FMC_DEVCLK: +FMC_DEVCLK_P -FMC_DEVCLK_N

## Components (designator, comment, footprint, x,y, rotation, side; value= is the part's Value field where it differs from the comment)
1P8USB "TESTPOINT" TESTPOINT#1 3687,819 r90 top
1V2ADC_INT "TSW-102-07-G-S" TSW-102-07-G-S 3842.27,2305 r0 top
1V2ADC_LDO "TSW-102-07-G-S" TSW-102-07-G-S 3535.27,2469 r180 top
1V9ADC "TSW-102-07-G-S" TSW-102-07-G-S 4847,2552.93 r90 top
1V9INT "TSW-102-07-G-S" TSW-102-07-G-S 4796,2319.07 r90 top
3P3RX "5011" Keystone5011 5455,515 r90 top
3P3USB "TESTPOINT" TESTPOINT#1 3005,419 r90 top
5VDC "PJ-202AH" CONN_CUI-PJ-202AH 539.37,235 r180 top
12V "LTST-C190GKT" LED_LTST-C190 5303.47,420 r180 top
C2 "GRM155R71A104KA01D" 0402L#1 3349,1210.67 r180 bottom
C7 "C0603X5R0J104K" 0201#1 1866.84,1682.81 r270 bottom
C8 "GRM155R71A104KA01D" 0402L#1 3304.32,985 r180 top
C9 "C0603X5R0J104K" 0201#1 1839.84,1682.81 r270 bottom
C10 "C0603X5R0J104K" 0201#1 2158.19,1474.14 r180 bottom
C11 "GRM155R71A104KA01D" 0402L#1 3379.32,1158 r180 bottom
C12 "C0603X5R0J104K" 0201#1 2158.19,1501.14 r180 bottom
C13 "C0603X5R0J104K" 0201#1 2068.19,1415.08 r180 bottom
C14 "C0603X5R0J104K" 0201#1 2068.19,1442.08 r180 bottom
C15 "C0603X5R0J104K" 0201#1 2158.19,1356.03 r180 bottom
C16 "C1005X5R0J475M050BC" 0402L#1 1783,1615.62 r270 bottom
C17 "C0603X5R0J104K" 0201#1 2158.19,1383.03 r180 bottom
C18 "C1005X5R1A104K" 0402L#1 1550.26,1251.2 r180 top
C19 "C1005X5R1A104K" 0402L#1 1545.2,1399.05 r180 top
C20 "C0603X5R0J104K" 0201#1 2068.19,1296.97 r180 bottom
C21 "C0603X5R0J104K" 0201#1 2068.19,1323.97 r180 bottom
C22 "C0603X5R0J104K" 0201#1 2158.19,1237.92 r180 bottom
C23 "C0603X5R0J104K" 0201#1 2158.19,1264.92 r180 bottom
C24 "0603YC104JAT2A" 0603L#1 1965.28,897.03 r90 bottom
C25 "06035A101JAT2A" 0603L#1 1965.28,897.03 r90 top
C26 "C0603X5R0J104K" 0201#1 2068.19,1178.86 r180 bottom
C27 "293D106X0010B2TE3" 3528-21 2090.28,889.42 r0 bottom
C28 "C0603X5R0J104K" 0201#1 2068.19,1205.86 r180 bottom
C29 "C0603X5R0J104K" 0201#1 1839.84,997.19 r90 bottom
C30 "C0603X5R0J224M" 0201#1 1382.58,1454.45 r180 bottom
C31 "C0603X5R0J104K" 0201#1 1866.84,997.19 r90 bottom
C32 "GRM033R61A472KA01D" 0201#1 1382.58,1454.45 r180 top
C33 "GRM033R61A472KA01D" 0201#1 1382.58,1481.45 r180 top
C34 "06035A101JAT2A" 0603L#1 1965.28,795 r90 top
C35 "GRM033R61A472KA01D" 0201#1 1583.93,1685 r90 top
C36 "C0603X5R0J224M" 0201#1 1382.58,1481.45 r180 bottom
C37 "GRM033R61A472KA01D" 0201#1 1610.93,1685 r90 top
C38 "06035A101JAT2A" 0603L#1 1916.28,777 r90 top
C39 "C1608X5R1A105K" 0603L#1 1626.96,1089.26 r270 top
C40 "C1608X5R1A105K" 0603L#1 1597.43,1590.74 r90 top
C41 "C0603X5R0J104K" 0201#1 1459.65,1280.94 r0 top
C42 "C0603X5R0J104K" 0201#1 1459.65,1379.37 r0 top
C43 "C0603X5R0J104K" 0201#1 1535.87,1438.43 r180 top
C44 "C0603X5R0J104K" 0201#1 1474.65,1497.48 r0 top
C45 "C0603X5R0J104K" 0201#1 1567.91,1590.74 r270 bottom
C46 "C0603X5R0J104K" 0201#1 1626.96,1590.74 r270 bottom
C47 "C0603X5R0J104K" 0201#1 1626.96,1089.26 r90 bottom
C48 "293D106X0010B2TE3" 3528-21 1503,1614 r90 top
C49 "C1608X5R1A105K" 0603L#1 1705.7,1089.26 r270 top
C50 "C1608X5R1A105K" 0603L#1 1686.02,1590.74 r90 top
C51 "C0603X5R0J104K" 0201#1 1459.65,1241.57 r0 top
C52 "C0603X5R0J104K" 0201#1 1538.57,1310.95 r180 top
C53 "C0603X5R0J104K" 0201#1 1535.87,1359.68 r180 top
C54 "C0603X5R0J104K" 0201#1 1459.65,1418.74 r0 top
C55 "C0603X5R0J104K" 0201#1 1686.02,1590.74 r270 bottom
C56 "C0603X5R0J104K" 0201#1 1745.07,1605.74 r270 bottom
C57 "C0603X5R0J104K" 0201#1 1725.39,1089.26 r90 bottom
C58 "C0603X5R0J104K" 0201#1 1686.01,1089.26 r90 bottom
C59 "293D106X0010B2TE3" 3528-21 1321.87,1103.87 r180 bottom
C60 "C1608X5R1A105K" 0603L#1 1853.34,1089.26 r270 top
C61 "C1608X5R1A105K" 0603L#1 1853.34,1590.74 r90 top
C62 "C0603X5R0J104K" 0201#1 1823.81,1089.26 r90 bottom
C63 "C0603X5R0J104K" 0201#1 1882.87,1089.26 r90 bottom
C64 "C0603X5R0J104K" 0201#1 1976.13,1221.89 r180 bottom
C65 "C0603X5R0J104K" 0201#1 1976.13,1280.95 r180 bottom
C66 "C0603X5R0J104K" 0201#1 1976.13,1340 r180 bottom
C67 "C0603X5R0J104K" 0201#1 1976.13,1399.05 r180 bottom
C68 "C0603X5R0J104K" 0201#1 1976.13,1458.11 r180 bottom
C69 "C0603X5R0J104K" 0201#1 1882.87,1590.74 r270 bottom
C70 "C0603X5R0J104K" 0201#1 1823.81,1590.74 r270 bottom
C71 "C0603X5R0J104K" 0201#1 1764.76,1529.51 r90 top
C72 "293D106X0010B2TE3" 3528-21 1986.39,1511.4 r0 top
C73 "C1005X5R1A104K" 0402L#1 3244,1659.68 r270 bottom
C74 "GRM1555C1E101JA01D" 0402L#1 3244,1659.68 r270 top
C75 "GRM1555C1H470JA01D" 0402L#1 2540.05,1919.81 r180 top
C76 "GRM1555C1H470JA01D" 0402L#1 2539.05,1660.18 r180 top
C77 "GRM155R71E103KA01D" 0402L#1 2572.36,1917 r180 bottom
C78 "GRM1555C1H270JA01D" 0402L#1 2572.36,1843.81 r180 bottom
C79 "GRM155R71E103KA01D" 0402L#1 2571.36,1678.5 r180 bottom
C80 "GRM1555C1H270JA01D" 0402L#1 2571.36,1620.82 r180 bottom
C81 "C1005X5R0J105M" 0402L#1 2572.36,1990 r180 bottom
C82 "C1005X5R0J105M" 0402L#1 2571.36,1736.18 r180 bottom
C83 "GRM1555C1H470JA01D" 0402L#1 2540.05,1883.18 r180 top
C84 "GRM1555C1H470JA01D" 0402L#1 2539.05,1696.81 r180 top
C85 "C1005X5R1A104K" 0402L#1 1662,2384 r180 top
C86 "C1005X5R1A104K" 0402L#1 1766.99,2519 r180 top
C87 "C1005X5R1A104K" 0402L#1 987.74,2141.68 r180 bottom
C88 "C1005X5R1A104K" 0402L#1 1756,2407 r90 top
C89 "C1005X5R1A104K" 0402L#1 968.06,2122 r270 top
C90 "GRM033R61A472KA01D" 0201#1 1583.93,1685 r90 bottom
C91 "GRM033R61A472KA01D" 0201#1 1610.93,1685 r90 bottom
C92 "GRM033R61A472KA01D" 0201#1 1395.57,1441.46 r270 bottom
C93 "GRM033R61A472KA01D" 0201#1 1395.57,1494.45 r90 bottom
C94 "GRM155R71A104KA01D" 0402L#1 5781,565 r270 top
C95 "GRM155R71A104KA01D" 0402L#1 2608,1190 r180 bottom
C96 "GRM155R71A104KA01D" 0402L#1 1935,1003.5 r90 bottom
C102 "C1005X7R1C103K" 0402L#1 1715.09,1977.24 r90 bottom
C103 "C1005X5R1A104K" 0402L#1 1855.32,1999.36 r180 bottom
C104 "C1005X5R1A104K" 0402L#1 1678.05,2486.05 r90 bottom
C105 "C1005X5R1A104K" 0402L#1 1774.14,2316.76 r270 bottom
C106 "C1005X5R1A104K" 0402L#1 1855.32,2078.1 r180 bottom
C107 "C1005X5R1A104K" 0402L#1 1647.92,2479.18 r90 bottom
C108 "C1608X5R1C105K" 0603L#1 1515.92,2316.76 r270 bottom
C109 "C1005X5R1A104K" 0402L#1 1679.72,1977.24 r90 bottom
C110 "C1005X5R1A104K" 0402L#1 1596.98,2316.76 r270 bottom
C111 "C1005X5R1A104K" 0402L#1 1855.32,2176.53 r180 bottom
C112 "C1005X5R1A104K" 0402L#1 1786.67,2437 r90 bottom
C113 "C1005X5R1A104K" 0402L#1 1820.67,2437 r90 bottom
C114 "C1005X5R1A104K" 0402L#1 1820.67,2437 r270 top
C115 "0603YC104JAT2A" 0603L#1 3566.49,1026 r0 bottom
C116 "06033C104JAT2A" 0603L#1 3422,2215 r90 top
C117 "06035A331JAT2A" 0603L#1 3780,2065 r270 top
C118 "C0603X5R0J104K" 0201#1 3331.72,215.03 r0 top
C119 "C0603X5R0J104K" 0201#1 3559.47,210.03 r0 top
C120 "C1005X5R1A104K" 0402L#1 1515.8,2215.9 r0 bottom
C121 "C1005X5R1A104K" 0402L#1 1515.8,1999.36 r0 bottom
C122 "C0805C106K8PACTU" 0805L 1668.9,1852.74 r270 top
C123 "C1005X5R1A104K" 0402L#1 1786.67,2437 r90 top
C124 "C1005X5R1A104K" 0402L#1 1719.3,1857.74 r270 top
C125 "C1608X5R1A105K" 0603L#1 3566.49,1026 r0 top
C126 "06033C104JAT2A" 0603L#1 3879.13,2150 r0 top
C127 "C0603C475K8PACTU" 0603L#1 4044.49,2090 r180 bottom
C128 "06031C103MAT2A" 0603L#1 4044.49,1940 r180 bottom
C129 "06033C104JAT2A" 0603L#1 4631.68,502.06 r180 top
C130 "06033C104JAT2A" 0603L#1 4719,490.31 r90 top
C131 "C0603X5R0J104K" 0201#1 3686.44,558.42 r90 top
C132 "C0603X5R0J104K" 0201#1 3420.31,781.24 r0 top
C133 "C0603X5R0J104K" 0201#1 3090.45,419.1 r180 top
C134 "C0603X5R0J104K" 0201#1 3670.44,394.5 r270 top
C135 "GRM1555C1H180JA01D" 0402L#1 3106.97,926 r180 top
C136 "C0603X5R0J104K" 0201#1 3233,795.02 r90 top
C137 "GRM1555C1H180JA01D" 0402L#1 3019.98,926 r0 top
C138 "GRM31CR60J107ME39L" 1206L 110.24,660.39 r270 bottom
C139 "C1608X5R1A106M" 0603L#1 3103.75,477.1 r180 bottom
C140 "C0603X5R0J104K" 0201#1 3090.45,468.32 r180 top
C141 "C1608X5R1A106M" 0603L#1 3133,606 r180 bottom
C142 "C0603X5R0J104K" 0201#1 3090.45,566.74 r180 top
C143 "C1608X5R1A105K" 0603L#1 4663.7,622 r0 top
C144 "06033C104JAT2A" 0603L#1 4472,1890 r0 bottom
C145 "EMK212BJ106KG-T" 0805L 5194,1262 r270 bottom
C146 "EMK212BJ106KG-T" 0805L 5194,1262 r270 top
C147 "06033C104JAT2A" 0603L#1 5253,1262 r270 top
C148 "06033C104JAT2A" 0603L#1 5354.27,1394 r270 top
C149 "06035A331JAT2A" 0603L#1 4568,2065 r270 top
C150 "C1608X5R1A106M" 0603L#1 4565,2150 r180 top
C151 "06033C104JAT2A" 0603L#1 4667.13,2150 r0 top
C152 "C1608X5R1A106M" 0603L#1 4472,1890 r0 top
C153 "06033C104JAT2A" 0603L#1 3442,1940 r180 top
C154 "06035A100JAT2A" 0603L#1 5334.44,1044 r180 top
C155 "C1608X5R1C105K" 0603L#1 5443,1044 r0 top
C156 "GRM31CR60J476ME19L" 1206L 5562,1658.75 r180 top
C157 "GRM31CR60J476ME19L" 1206L 5562,1658.75 r180 bottom
C158 "C1608X5R1A106M" 0603L#1 5565.94,1802 r180 bottom
C159 "06033C104JAT2A" 0603L#1 5565.94,1802 r180 top
C160 "C0603C475K8PACTU" 0603L#1 4832.49,2090 r180 bottom
C161 "06031C103MAT2A" 0603L#1 4832.49,1940 r180 bottom
C162 "GRM188R71E332KA01D" 0603L#1 5547,1109.54 r0 top
C163 "C1608X5R1A106M" 0603L#1 3442,1940 r180 bottom
C164 "06033C104JAT2A" 0603L#1 3494,2345.06 r90 top
C165 "C1608X5R1A106M" 0603L#1 3494,2345.06 r90 bottom
C166 "C1608X5R1A106M" 0603L#1 3777,2150 r180 top
C167 "06033C104JAT2A" 0603L#1 4417,1319.27 r270 top
C168 "C1608X7R1C224K" 0603L#1 4393,1716 r90 top
C169 "GRM155R60J104KA01D" 0402L#1 4490.74,1361 r270 top
C170 "GRM155R60J104KA01D" 0402L#1 4343.26,1361 r90 top
C171 "C1608X5R1A106M" 0603L#1 3422,2215 r90 bottom
C172 "C1608X5R1A106M" 0603L#1 3962.67,2437 r90 top
C173 "EMK212BJ106KG-T" 0805L 4376.5,1319.27 r270 bottom
C174 "GRM188R71C273KA01D" 0603L#1 4585,1716 r90 top
C175 "GRM188R71C273KA01D" 0603L#1 4249,1716 r270 top
C176 "06033C104JAT2A" 0603L#1 3861.41,1084 r0 top
C177 "06033C104JAT2A" 0603L#1 3275.44,2341.5 r180 top
C178 "06033C393KAT2A" 0603L#1 4489,1716 r90 top
C179 "06033C393KAT2A" 0603L#1 4345,1716 r90 top
C180 "GRM31CR61A226ME19L" 1206L 4995,1283 r180 top
C181 "GRM31CR61A226ME19L" 1206L 4995,1283 r180 bottom
C182 "GRM31CR61A226ME19L" 1206L 3887,1283 r0 top
C183 "GRM31CR61A226ME19L" 1206L 3887,1283 r0 bottom
C184 "EMK212BJ106KG-T" 0805L 4457.5,1319.27 r270 bottom
C185 "06033C104JAT2A" 0603L#1 3670.68,2418 r270 top
C186 "C1608X5R1A106M" 0603L#1 3962.68,2539 r270 top
C187 "06035A561JAT2A" 0603L#1 3769.68,2558.87 r270 bottom
C188 "C1608X5R1A106M" 0603L#1 3214,2406.01 r180 top
C189 "06033C104JAT2A" 0603L#1 3418.56,2341.5 r0 top
C190 "C1608X5R1A106M" 0603L#1 3861.41,1084 r0 bottom
C191 "06033C104JAT2A" 0603L#1 5015.5,2513.93 r270 top
C192 "GRM188R71C472KA01D" 0603L#1 4711,2536.39 r90 top
C193 "EEU-EB1E101S" CAPPR250W50D630H1120 1863,153.54 r270 top
C194 "GRM32DC81E106KA12L" 1210L 2062.3,73.49 r0 bottom
C195 "C1608X5R1A106M" 0603L#1 3670.68,2418 r270 bottom
C196 "C1608X5R1A106M" 0603L#1 4711,2402.53 r90 top
C197 "C1608X5R1A106M" 0603L#1 3418.56,2292.5 r0 top
C198 "06033C104JAT2A" 0603L#1 4759,2536.39 r90 top
C199 "06033C104JAT2A" 0603L#1 5020.59,1084 r180 top
C200 "C1608X5R1A106M" 0603L#1 3586.26,789.7 r0 top
C201 "C1608X5R1C105K" 0603L#1 329.24,689.56 r270 bottom
C202 "C1608X5R1A106M" 0603L#1 5015.5,2513.93 r270 bottom
C203 "C1608X5R1A106M" 0603L#1 5020.59,1084 r180 bottom
C204 "C1608X5R1A106M" 0603L#1 4759,2536.39 r90 bottom
C205 "C1608X5R1A105K" 0603L#1 3610,567 r90 bottom
C206 "C1005X5R1A104K" 0402L#1 1833.2,2316.76 r270 bottom
C207 "C1005X5R1A104K" 0402L#1 1715.09,2316.76 r270 bottom
C208 "C1005X5R1A104K" 0402L#1 1656.03,2316.76 r270 bottom
C209 "C1005X5R1A104K" 0402L#1 1557.61,2316.76 r270 bottom
C210 "0603YC104JAT2A" 0603L#1 111.3,839 r0 bottom
C211 "C1608X5R1C105K" 0603L#1 228.7,775.86 r0 bottom
C212 "GRM31CR60J107ME39L" 1206 3495,846 r0 bottom
C213 "06033C104JAT2A" 0603L#1 3528,407.69 r270 bottom
C214 "C0603X5R0J104K" 0201#1 3502.59,781.24 r180 top
C215 "GRM155R71A104KA01D" 0402L#1 2060,1726 r180 top
C216 "GRM155R71A104KA01D" 0402L#1 2403,1842 r0 top
C217 "GRM155R71A104KA01D" 0402L#1 3612.55,1790 r180 top
C218 "GRM155R71A104KA01D" 0402L#1 3097,1040 r180 top
C219 "GRM155R71A104KA01D" 0402L#1 3770.85,1090 r180 top
C220 "GRM155R71A104KA01D" 0402L#1 4035,990 r0 bottom
C221 "GRM155R71A104KA01D" 0402L#1 3950,1090 r0 bottom
C222 "GRM155R71A104KA01D" 0402L#1 5116,1090 r0 top
C223 "GRM155R71A104KA01D" 0402L#1 4688,1090 r180 bottom
C224 "GRM155R71A104KA01D" 0402L#1 3766,1790 r180 bottom
C225 "GRM155R71A104KA01D" 0402L#1 3950,1790 r0 bottom
C226 "GRM155R71A104KA01D" 0402L#1 4904,1790 r0 bottom
C227 "GRM155R71A104KA01D" 0402L#1 4688,1790 r180 bottom
C228 "500R07S0R5BV4T" 0402L#1 1155.85,1611.45 r270 bottom
C229 "500R07S0R5BV4T" 0402L#1 1155.85,1538.46 r90 bottom
C230 "GRM1885C1H470JA01D" 0603L#1 3173.33,1739.79 r270 bottom
C231 "C1005X5R1A104K" 0402L#1 3136.33,1740.79 r90 bottom
C232 "C1005X5R0J105M" 0402L#1 3106.33,1740.79 r270 bottom
C233 "GRM1555C1H4R7CA01D" 0402L#1 3076.33,1740.79 r270 bottom
C234 "GRM1885C1H470JA01D" 0603L#2 3173.33,1739.79 r270 top
C235 "C1005X5R1A104K" 0402L#1 3136.33,1740.79 r90 top
C236 "C1005X5R0J105M" 0402L#1 3106.33,1740.79 r270 top
C237 "GRM1555C1H4R7CA01D" 0402L#1 3076.33,1740.79 r270 top
C238 "GRM1555C1H4R7CA01D" 0402L#1 2980.24,1614.68 r0 top
C239 "GRM155R71E103KA01D" 0402L#1 2980.24,1584.68 r0 top
C240 "C1005X5R0J105M" 0402L#1 2980.24,1554.68 r0 top
C241 "GRM1555C1H4R7CA01D" 0402L#1 2902.24,1614.68 r180 top
C242 "GRM155R71E103KA01D" 0402L#1 2902.24,1584.68 r180 top
C243 "C1005X5R0J105M" 0402L#1 2902.24,1554.68 r180 top
C244 "GRM1555C1H561JA01D" 0402L#1 3130.29,1619.31 r180 top
C245 "GRM1555C1H470JA01D" 0402L#1 3130.29,1658.68 r180 top
C246 "GRM1555C1H4R7CA01D" 0402L#1 3090.92,1547.31 r180 top
C247 "GRM1555C1H2R2CA01D" 0402L#2 3090.92,1443 r180 top
C248 "GRM1555C1H4R7CA01D" 0402L#1 2845.02,1616 r270 top
C249 "GRM1555C1H220JA01D" 0402L#1 3071.33,1813.69 r0 top
C250 "C1005X5R1A104K" 0402L#1 2901,2179.37 r0 top
C251 "C1005X5R1A104K" 0402L#1 3071.33,1844 r0 top
C252 "C1005X5R0J105M" 0402L#1 2969.43,1989.09 r0 top
C253 "GRM155R71E103KA01D" 0402L#1 2969.43,1959.09 r0 top
C254 "GRM1555C1H270JA01D" 0402L#1 2969.43,1929.09 r0 top
C255 "C1005X5R0J105M" 0402L#1 2819.04,1989.09 r180 top
C256 "GRM155R71E103KA01D" 0402L#1 2819.04,1959.09 r180 top
C257 "GRM1555C1H270JA01D" 0402L#1 2819.04,1929.09 r180 top
C258 "C1005X5R1A104K" 0402L#1 2211.16,1544.09 r0 top
C259 "C1005X5R1A104K" 0402L#1 1878.91,2564.56 r270 top
C260 "C1005X5R1A104K" 0402L#3 1694,2537.87 r0 bottom
C261 "GRM155R71A104KA01D" 0402L#1 5806,1790 r0 top
C262 "GRM033R61A472KA01D" 0201#2 1395.57,1441.46 r270 top
C263 "GRM033R61A472KA01D" 0201#2 1395.57,1494.45 r90 top
C264 "LLL185R71E103MA01L" 0306 837.19,1216.52 r90 top
C265 "LLL185R71E103MA01L" 0306 930.03,1216.52 r270 top
C266 "LLL185R71H222MA01L" 0306 837.19,1216.52 r270 bottom
C267 "LLL185R71H222MA01L" 0306 930.03,1216.52 r90 bottom
C268 "LLL185R71H222MA01L" 0306 837.19,1443.79 r90 bottom
C269 "LLL185R71H222MA01L" 0306 930.03,1443.79 r270 bottom
C270 "LLL185R71E103MA01L" 0306 837.19,1443.79 r270 top
C271 "LLL185R71E103MA01L" 0306 930.03,1443.79 r90 top
C272 "C1005X7R1E103K" 0402L#1 903.3,1160 r180 bottom
C273 "C1005X5R1A104K" 0402L#1 883.61,1284.88 r180 top
C274 "C1005X5R1A104K" 0402L#1 883.61,1375.43 r180 top
C275 "TPSA106K010R0900" 3216-18 80,1479.94 r270 bottom
C276 "C1608X5R1A106M" 0603L#1 419.29,1661.52 r0 top
C277 "06033C104JAT2A" 0603L#1 419.29,1709.52 r0 top
C278 "06031C103MAT2A" 0603L#3 534.99,1830.21 r270 top
C279 "C0603C150J5GACTU" 0603L#1 419.29,1960.52 r0 top
C280 "C1608X5R1A106M" 0603L#1 291.99,1830.21 r270 top
C281 "06033C104JAT2A" 0603L#1 340.99,1830.21 r270 top
C282 "C1608X5R1A106M" 0603L#1 204.73,1322.99 r0 top
C283 "06033C104JAT2A" 0603L#1 204.73,1278.99 r0 top
C284 "C1608X5R0J226M080AC" 0603L#1 295.73,1186.99 r90 top
C285 "C1608X5R0J226M080AC" 0603L#1 295.73,1288.99 r270 top
C286 "GRM1555C1H100JA01D" 0402L#1 64.73,1344.99 r180 top
C287 "GRM188R61A225KE34D" 0603L#1 453.63,1175 r0 top
C288 "06033C104JAT2A" 0603L#1 453.63,1224 r0 top
C289 "C1608X5R1A106M" 0603L#1 443,1408 r180 top
C290 "06033C104JAT2A" 0603L#1 443,1457 r180 top
C291 "GRM1555C1H1R0CA01D" 0402L#4 1063.79,1293.66 r90 bottom
C292 "GRM1555C1H1R0CA01D" 0402L#5 1063.79,1366.66 r90 bottom
C293 "GRM1555C1H2R7CA01D" 0402L#1 1179.1,1293.66 r90 bottom
C294 "GRM1555C1H2R7CA01D" 0402L#1 1179.1,1366.66 r90 bottom
C295 "Used in BOM report" 0402L#6 680.41,1263 r270 bottom
C296 "Used in BOM report" 0402L#6 680.41,1397.31 r90 bottom
D1 "PMEG3005EL,315" SOD882 198.73,1237.99 r0 top
D2 "1N4148W-7-F" SOD-123 3179.48,1165 r180 bottom
D4 "1N4148W-7-F" SOD-123 3179.48,1115 r180 top
D11 "MBRS540T3G" SMC 4661,1191 r0 top
D12 "MBRS540T3G" SMC 4173,1191 r180 top
DEVCLK "SASF546-P26-X1" CONN_LTI_SASF546-P26-X1 968.06,2322 r0 top
EXT5V_FMC12V "PBC03SAAN" PBC03SAAN 5308,90 r0 top
EXT_Vcmo "TSW-102-07-G-S" TSW-102-07-G-S 1169.78,727 r90 top
EXT_VCO "SASF546-P26-X1" CONN_LTI_SASF546-P26-X1 2784.02,1040 r270 top
FID1 "Fiducial" Fiducial10-30 354,2592 r0 top
FID2 "Fiducial" Fiducial10-30 38,478 r0 top
FID3 "Fiducial" Fiducial10-30 6213,2592 r0 top
FMC_RX1 "ASP-134488-01" CONN_SEARAY_ASP-134488-01 5981,1341.94 r90 bottom locked
FTDI_3P3V "TSW-103-07-G-S" TSW-103-07-G-S 2179.28,426 r180 top
GND "5011" Keystone5011 1062,1945 r0 top
GND1 "5011" Keystone5011 3153,2576 r0 top
GND2 "5011" Keystone5011 5610,95 r0 top
GND3 "5011" Keystone5011 5209,2526 r0 top
H3 "1648-440-AL" Keystone_1902C 542,580 r180 bottom
H4 "1648-440-AL" Keystone_1902C 600,2505 r180 bottom
H5 "NY PMS 440 0025 PH" "NY PMS 440 0025 PH"#1 542,580 r0 top
H6 "NY PMS 440 0025 PH" "NY PMS 440 0025 PH"#2 600,2505 r0 top
J1 "TSW-104-07-G-S" TSW-104-07-G-S 4514,690 r270 top
J2 "TSW-102-07-G-S" TSW-102-07-G-S 3294,1415 r180 top
J3 "TSW-102-07-G-S" TSW-102-07-G-S 3963,690 r90 top
"KC705 JTAG" "TSW-102-07-G-S" TSW-102-07-G-S 5472,915 r180 top
L1 "BLM15HG102SN1D" 0402L#1 2572.36,1790 r0 bottom
L2 "BLM18SG331TN1D" 0603 1904.42,1932.5 r180 bottom
L3 "BLM18SG331TN1D" 0603 1701.46,2396.5 r0 bottom
L4 "BLM18SG331TN1D" 0603 1935.92,2035.92 r90 bottom
L5 "BLM18SG331TN1D" 0603 1596.98,2428 r270 bottom
L6 "BLM18SG260TN1D" 0603 4382,1908 r270 top
L7 "BLM18SG121TN1D" 0603 5562,1739.21 r0 top
L8 "CDRH6D28NP-3R0NC" CDRH6D28 5311,1614 r90 top
L9 "BLM18SG260TN1D" 0603 3562.5,1940 r180 top
L10 "BLM18SG260TN1D" 0603 3494,2134.5 r90 top
L11 "MSS1038-702NLB" MSS1038 4881,1571 r180 top
L12 "744325550" WE-HC6 3930,1571 r180 top
L13 "BLM18SG260TN1D" 0603 3422,2071.5 r90 top
L14 "BLM18SG121TN1D" 0603 3833.85,1175 r270 top
L15 "BLM18SG260TN1D" 0603 3303,2437.5 r270 top
L16 "BLM18SG260TN1D" 0603 3391,2437.5 r270 top
L17 "BLM18SG260TN1D" 0603 1977.65,202.76 r0 bottom
L18 "BLM18SG260TN1D" 0603 4979,2602.93 r0 top
L19 "BLM18SG331TN1D" 0603 1935.92,2218.71 r270 bottom
L20 "BLM18SG121TN1D" 0603 5048.15,1175 r270 top
L21 "BLM18SG331TN1D" 0603 1437.5,2247.39 r270 bottom
L22 "BLM18SG331TN1D" 0603 1437.5,2030.86 r270 bottom
L23 "BLM18SG331TN1D" 0603 3728,251 r0 top
L24 "BLM18SG121TN1D" 0603 3221,491 r180 bottom
L25 "BLM18SG121TN1D" 0603L#1 3160.56,682 r270 bottom
L26 "BLM18SG260TN1D" 0603 115.24,775.86 r180 bottom
L27 "BLM15HG102SN1D" 0402L#1 3211,1710.99 r90 bottom
L28 "BLM15HG102SN1D" 0402L#7 3229.84,1733.13 r180 top
L29 "BLM15HG102SN1D" 0402L#1 2960.55,1502.68 r90 top
L30 "BLM15HG102SN1D" 0402L#1 2921.92,1502.68 r90 top
L31 "BLM15HG102SN1D" 0402L#1 3444,1415 r180 top
L32 "BLM15HG102SN1D" 0402L#1 2969.43,2019.09 r180 top
L33 "BLM15HG102SN1D" 0402L#1 2819.04,2019.09 r0 top
L34 "BLM15HG102SN1D" 0402L#1 2646,1620.82 r180 bottom
L35 "BLM18SG121TN1D" 0603 391.73,1565.52 r90 top
L36 "BLM18SG121TN1D" 0603 177.17,1419 r270 top
L37 "VLS2012ET-6R8M" VLS2012 207.94,1148.49 r0 top
L38 "0603HC-6N8XJLU" 0603HC 1121.44,1273.97 r0 bottom
L39 "0603HC-6N8XJLU" 0603HC 1121.44,1386.34 r0 bottom
L40 "0603HC-3N6XJLU" 0603HC 1236.75,1273.97 r0 bottom
L41 "0603HC-3N6XJLU" 0603HC 1236.75,1386.34 r0 bottom
L42 "BLM18SG121TN1D" 0603 358,1206.49 r270 top
L43 "BLM18SG121TN1D" 0603 335,1952 r270 top
L44 "BLM18SG121TN1D" 0603 564.79,1413.99 r180 top
LD "LTST-C190GKT" LED_LTST-C190 2891.16,2235.37 r180 top
LD1 "TESTPOINT" TESTPOINT#1 2149.93,2181 r270 top
LD2 "TESTPOINT" TESTPOINT#1 1286,2561 r180 top
LF1 "C1608C0G1E392J" 0603L#1 1517.3,2436.74 r180 top
LF2 "06035A470JAT2A" 0603L#1 1517.3,2386.74 r180 top
LF3 "RC0603FR-07619RL" 0603L#1 1437.86,2409.18 r90 top
LF7 "ACM7060-301-2PL-TL" IND_TDK_ACM7060 1523.5,153.54 r0 bottom
"LMH PD" "TSW-102-07-G-S" TSW-102-07-G-S 773,1987 r180 top
LMK_INT "TSW-102-07-G-S" TSW-102-07-G-S 4207,2040 r180 top
LMK_LDO "TSW-102-07-G-S" TSW-102-07-G-S 3644,2040 r180 top
LMKCLK "SASF546-P26-X1" CONN_LTI_SASF546-P26-X1 2079.5,2482.51 r0 top
LMX_INT "TSW-102-07-G-S" TSW-102-07-G-S 4995,2040 r180 top
LMX_LDO "TSW-102-07-G-S" TSW-102-07-G-S 4432,2040 r180 top
LO2_N "TESTPOINT" TESTPOINT#2 2641.05,1833.99 r90 top
LO2_P "TESTPOINT" TESTPOINT#2 2641.05,1796.01 r90 top
LO3_N "TESTPOINT" TESTPOINT#2 2691.32,1728 r90 top
LO3_P "TESTPOINT" TESTPOINT#2 2654.69,1728 r90 top
Logo1 "ESD Susceptible" ESD_Overlay_Small 5416,1930 r0 top
Logo2 "Texas Instruments" TI_Symbol_Overlay_Small 5202,2277 r0 top
Logo3 "Pb-Free Symbol" Pb-Free_Overlay_Small 5275,2062 r0 top
Logo4 "FCC disclaimer" FCC_disclaimer 6080,1559 r90 top
LOGO5 "CAUTION HOT SURFACE" IEC_HotSurface_Small 2310,1340 r180 bottom
NCO "TSW-103-07-G-D" TSW-103-07-G-D 2433.5,1140 r0 top
OR "TSW-103-07-G-S" TSW-103-07-G-S 2117.5,2015 r180 top
OR_T0 "LTST-C190KFKT" LED_LTST-C190 3575,1232.52 r0 top
OR_T1 "LTST-C190KFKT" LED_LTST-C190 3575,1090 r0 top
OSCin "SASF546-P26-X1" CONN_LTI_SASF546-P26-X1 3161.24,2125 r0 top
PG_RX1 "TSW-102-07-G-S" TSW-102-07-G-S 5506,2559 r180 top
R1 "CRCW04028K06FKED" 0402L#1 3458,1140 r0 bottom
R2 "CRCW04021K20JNED" 0402L#1 3604.53,1212.84 r270 bottom
R3 "CRCW04021M00JNED" 0402L#1 3349,1254.36 r0 bottom
R4 "CRCW060310K0FKEA" 0603L#1 2980.5,1090 r180 top
R5 "CRCW060310K0FKEA" 0603L#1 2433.5,1004 r90 bottom
R6 "CRCW060310K0FKEA" 0603L#1 2333.5,1004 r90 bottom
R7 "ERJ-1GE0R00C" 0201#1 2145.2,1224.93 r90 bottom
R8 "ERJ-1GE0R00C" 0201#1 2055.2,1165.87 r90 bottom
R9 "ERJ-1GE0R00C" 0201#1 1826.85,1010.18 r0 bottom
R10 "CRCW04021K20JNED" 0402L#1 3604.53,1109.68 r90 bottom
R11 "CRCW04021M00JNED" 0402L#1 3304.32,950 r0 top
R12 "CRCW04021K33FKED" 0402L#1 3379.32,1122 r0 bottom
R13 "RG1608P-332-B-T5" 0603L#1 1498.26,1175 r180 top
R14 "CRCW060310K0FKEA" 0603L#1 2293.28,858.81 r0 top
R15 "CRCW060310K0FKEA" 0603L#1 2293.28,811.41 r0 top
R16 "CRCW060310K0FKEA" 0603L#1 2293.28,763.41 r0 top
R17 "RC0603JR-07750RL" 0603L#1 2293.28,763.41 r0 bottom
R18 "ERJ-1GE0R00C" 0201#1 1642.99,1694 r90 bottom
R19 "ERJ-1GE0R00C" 0201#1 1642.99,1694 r90 top
R20 "ERJ-1GE0R00C" 0201#1 1669.99,1694 r90 top
R21 "ERJ-1GE0R00C" 0201#1 1669.99,1694 r90 bottom
R22 "ERJ-1GE0R00C" 0201#1 1656,1653 r0 top
R23 "ERJ-1GE0R00C" 0201#1 1697,1666 r270 top
R24 "CRCW040210K0FKED" 0402L#1 3071.33,1879.09 r0 top
R25 "ERJ-2GE0R00X" 0402L#1 3091.02,1931.09 r270 top
R26 "ERJ-2GE0R00X" 0402L#1 3538.47,1659.68 r270 top
R27 "CRCW0402100RFKED" 0402L#1 2592.05,1939.5 r270 top
R28 "CRCW0402100RFKED" 0402L#1 2591.05,1640.5 r90 top
R29 "ERJ-2GE0R00X" 0402L#1 2488.05,1939.5 r270 top
R30 "CRCW040249R9FKED" 0402L#1 3051.65,1931.09 r90 top
R31 "RC0603JR-071K3L" 0603L#1 2293.28,811.41 r0 bottom
R32 "RC0603JR-071K3L" 0603L#1 2293.28,858.81 r0 bottom
R33 "CRCW04023K30JNED" 0402L#1 2488.05,1640.5 r90 bottom
R34 "CRCW0402100RFKED" 0402L#1 2592.05,1863.5 r90 top
R35 "CRCW0402100RFKED" 0402L#1 2591.05,1716.5 r270 top
R36 "ERJ-2GE0R00X" 0402L#1 2488.05,1863.5 r90 top
R37 "CRCW04023K30JNED" 0402L#1 2488.05,1716.5 r270 bottom
R38 "ERJ-2GE0R00X" 0402L#1 3150,1813.68 r0 top
R39 "RC0603JR-071KL" 0603L#1 3753,1940 r0 top
R40 "CSNL1206FT2L00" 1206 3644,2135.44 r180 bottom
R41 "CRCW060310K7FKEA" 0603L#1 3780,2065 r90 bottom
R42 "CSNL1206FT2L00" 1206 4207,2135.44 r180 bottom
R43 "CRCW04020000Z0ED" 0402L#1 1358.78,2106 r180 top
R44 "CRCW04020000Z0ED" 0402L#1 1358.78,2140 r180 top
R45 "CRCW0603270RJNEA" 0603L#1 1388.5,2625 r0 top
R47 "RC0603FR-072K32L" 0603L#1 1619.79,1890 r180 bottom
R48 "CRCW04020000Z0ED" 0402L#1 1843.67,2488.35 r0 top
R49 "RC0603FR-074K64L" 0603L#1 3855,2037.44 r180 bottom
R50 "Used in BOM report" 0402L#1 1766.99,2489 r180 top
R51 "CRCW040251R0JNED" 0402L#1 1900.67,2462.82 r90 top
R52 "CRCW060310R0JNEA" 0603L#1 957.8,531.69 r0 top
R53 "CRCW060310R0JNEA" 0603L#1 957.8,483.69 r0 top
R54 "CRCW0603100RJNEA" 0603L#1 4822.56,263.94 r270 bottom
R55 "CRCW0603100RJNEA" 0603L#1 4767.44,263.94 r270 bottom
R56 "CRCW0603270RJNEA" 0603L#1 2215.5,2267.95 r180 top
R57 "CRCW0603100RJNEA" 0603L#1 4767.44,487.44 r90 bottom
R58 "CRCW0603100RJNEA" 0603L#1 4822.56,466.06 r90 bottom
R59 "CRCW04020000Z0ED" 0402L#1 1975.56,2164 r0 top
R60 "CRCW04020000Z0ED" 0402L#1 1975.56,2130 r0 top
R61 "CRCW04020000Z0ED" 0402L#1 1800.98,1857 r270 top
R62 "CRCW04020000Z0ED" 0402L#1 1766.98,1857 r270 top
R63 "CRCW04020000Z0ED" 0402L#1 1564.76,1857 r270 top
R64 "CRCW04020000Z0ED" 0402L#1 1530.76,1857 r270 top
R65 "CRCW0603100RJNEA" 0603L#1 4631.68,229 r0 top
R66 "CRCW06031K00FKEA" 0603L#1 3070.47,351.73 r180 top
R67 "RC0603FR-0712KL" 0603L#1 3018.47,575.52 r270 top
R68 "CRCW0603100RJNEA" 0603L#1 3885.44,440 r180 top
R69 "CRCW0603100RJNEA" 0603L#1 3988,440 r0 bottom
R70 "RC0603JR-0710KL" 0603L#1 5288.19,1164.85 r270 bottom
R71 "RC0603JR-071KL" 0603L#1 4541,1940 r0 top
R72 "RC0603FR-0795K3L" 0603L#1 5334.44,995 r0 top
R73 "CSNL1206FT2L00" 1206 4432,2135.44 r180 bottom
R74 "CRCW060310K7FKEA" 0603L#1 4568,2065 r90 bottom
R75 "CSNL1206FT2L00" 1206 4995,1944.56 r180 bottom
R76 "CRCW060322K1FKEA" 0603L#1 5443,995 r180 top
R77 "RC0603FR-074K64L" 0603L#1 4643,2037.44 r180 bottom
R78 "RC0603FR-0710RL" 0603L#1 4441,1716 r270 top
R79 "CRCW0603732RFKEA" 0603L#1 4011.68,2539 r270 top
R80 "RC0603JR-071KL" 0603L#1 3927.66,2631 r180 top
R81 "CRCW060316K2FKEA" 0603L#1 4585,1716 r270 bottom
R82 "CRCW06037K87FKEA" 0603L#1 4249,1716 r90 bottom
R83 "CSNL1206FT2L00" 1206 3842.27,2209.56 r0 bottom
R84 "CSNL1206FT2L00" 1206 3535.27,2564.44 r180 bottom
R85 "CRCW06032K49FKEA" 0603L#1 3670.68,2520 r270 top
R86 "CRCW06035K90FKEA" 0603L#1 4537,1716 r270 top
R87 "CRCW06035K90FKEA" 0603L#1 4297,1716 r270 top
R88 "CRCW06034K99FKEA" 0603L#1 3694.68,2547.56 r180 bottom
R89 "CRCW06032K80FKEA" 0603L#1 3872.36,2558.87 r90 bottom
R90 "RC0603FR-07402RL" 0603L#1 3962.68,2539 r90 bottom
R91 "CRCW04024K99FKED" 0402L#1 3149.98,1567 r270 top
R92 "CSNL1206FT2L00" 1206 4942.44,2552.93 r90 bottom
R93 "RC0603FR-071KL" 0603L#1 4711,2536.39 r270 bottom
R94 "CRCW12061K00JNEA" 1206L 5308,289 r270 top
R95 "CSNL1206FT2L00" 1206 4891.44,2319.07 r90 bottom
R96 "RC0603FR-07357RL" 0603L#1 4735,2612 r180 top
R97 "CRCW060312K4FKEA" 0603L#1 3988,540 r0 top
R98 "CRCW060312K4FKEA" 0603L#1 3988,440 r0 top
R99 "ERJ-3GEY0R00V" 0603L#1 1923,737 r0 bottom
R100 "ERJ-3GEY0R00V" 0603L#1 1923,817 r0 bottom
R101 "CRCW060312K4FKEA" 0603L#1 3988,340 r0 top
R102 "CRCW060312K4FKEA" 0603L#1 3988,240 r0 top
R103 "CRCW06030000Z0EA" 0603L#1 329.24,811.96 r270 bottom
R104 "CRCW040224K0JNED" 0402L#1 3980.13,398 r180 top
R105 "CRCW060310K0FKEA" 0603L#1 3379.32,735 r90 bottom
R106 "CRCW060310K0FKEA" 0603L#1 3316.2,815 r90 top
R107 "CRCW060310K0FKEA" 0603L#1 3268.2,815 r90 top
R108 "RC0603JR-072K2L" 0603L#1 3406.88,659 r180 bottom
R109 "CRCW0603100RJNEA" 0603L#1 4795,438.5 r180 top
R110 "CRCW0603100RJNEA" 0603L#1 4795,340.5 r180 top
R111 "CRCW0603100RJNEA" 0603L#1 4795,389.5 r180 top
R112 "CRCW0603270RJNEA" 0603L#1 2978.91,273.24 r270 top
R113 "CRCW0603100RJNEA" 0603L#1 3886,540 r180 top
R114 "CRCW0603100RJNEA" 0603L#1 3885.44,298 r180 top
R115 "CRCW0603100RJNEA" 0603L#1 3932.88,157.56 r180 top
R116 "CRCW040224K0JNED" 0402L#1 3933.24,498 r180 top
R117 "CRCW0603100RJNEA" 0603L#1 3622.26,392.13 r180 bottom
R118 "CRCW0603100RJNEA" 0603L#1 4795,291.5 r180 top
R119 "CRCW0603100RJNEA" 0603L#1 3988,540 r0 bottom
R120 "CRCW0603100RJNEA" 0603L#1 3988,340 r0 bottom
R121 "CRCW0603100RJNEA" 0603L#1 3988,240 r0 bottom
R122 "RC0603JR-071K3L" 0603L#1 1590.93,1966.24 r270 bottom
R123 "CRCW060310K0FKEA" 0603L#1 4719,290.53 r270 top
R124 "CRCW0603100RJNEA" 0603L#1 3725,369.57 r270 top
R125 "CRCW0603100RJNEA" 0603L#1 3776.56,369.57 r270 top
R126 "CRCW0603100RJNEA" 0603L#1 3753,445 r0 top
R127 "CRCW0603100RJNEA" 0603L#1 3804.12,397.13 r0 bottom
R128 "CRCW040224K0JNED" 0402L#1 3980.13,298 r180 top
R129 "CRCW040224K0JNED" 0402L#1 3980.13,282 r180 bottom
R130 "CRCW060310K0FKEA" 0603L#1 3768,522.46 r270 bottom
R131 "CRCW060310K0FKEA" 0603L#1 3719,542.15 r270 bottom
R132 "CRCW06030000Z0EA" 0603L#1 5588,515 r0 top
R133 "CRCW04021K00FKED" 0402L#1 3391.24,1640 r180 bottom
R134 "RC0603JR-071KL" 0603L#1 1918,1754 r180 bottom
R135 "CRCW06032K10FKEA" 0603L#1 1938.64,1678.24 r90 bottom
R136 "CRCW06034K70JNEA" 0603L#1 2383.5,1302 r90 top
R137 "CRCW06034K70JNEA" 0603L#1 2511.06,1276 r0 top
R138 "CRCW06034K70JNEA" 0603L#1 2980.5,1040 r0 top
R139 "CRCW06032K00JNEA" 0603L#1 5081.44,292.56 r270 bottom
R140 "CRCW06032K00JNEA" 0603L#1 5081.44,392.56 r270 bottom
R141 "CRCW06032K00JNEA" 0603L#1 5081.44,492.56 r270 bottom
R142 "ERJ-3GEY0R00V" 0603L#1 1918,1843 r180 bottom
R143 "ERJ-3GEY0R00V" 0603L#1 1918,1798.5 r180 bottom
R144 "CRCW040210K0FKED" 0402L#8 3090.92,1588 r0 top
R145 "ERJ-2GE0R00X" 0402L#9 3071.24,1639 r270 top
R146 "ERJ-2GE0R00X" 0402L#1 3012,1432.5 r0 top
R147 "ERJ-2GE0R00X" 0402L#1 3012,1397.5 r180 top
R148 "ERJ-2GE0R00X" 0402L#9 3110.61,1494 r270 top
R149 "ERJ-2GE0R00X" 0402L#8 3058.24,1494 r90 top
R150 "CRCW04021M00JNED" 0402L#1 3149.98,1494 r90 top
R151 "CRCW06030000Z0EA" 0603L#1 2735,1615 r0 top
R152 "CRCW06030000Z0EA" 0603L#1 2735,1565 r180 top
R153 "CRCW040249R9FKED" 0402L#1 2825.34,1540 r0 top
R154 "CRCW0402261RFKED" 0402L#1 2957,2159.68 r270 top
R156 "CRCW0402127RFKED" 0402L#1 1840.36,2519 r0 bottom
R157 "CRCW0402127RFKED" 0402L#1 1766.99,2519 r180 bottom
R158 "CRCW040282R5FKED" 0402L#1 1840.36,2489 r180 bottom
R159 "CRCW040282R5FKED" 0402L#1 1766.99,2489 r0 bottom
R160 "CRCW04020000Z0ED" 0402L#1 1358.78,2193.37 r180 top
R161 "CRCW04020000Z0ED" 0402L#1 1358.78,2227.37 r180 top
R162 "CRCW0402107RFKED" 0402L#10 2488.05,1678.5 r270 top
R163 "CRCW04022K20JNED" 0402L#1 2519.36,1640.5 r270 bottom
R164 "CRCW04022K20JNED" 0402L#1 2519.36,1716.5 r90 bottom
R165 "CRCW040251R0JNED" 0402L#1 948.37,2141.68 r0 top
R166 "CRCW0402560RJNED" 0402L#1 1415.24,2123 r270 top
R167 "CRCW0402560RJNED" 0402L#1 1415.24,2210.37 r270 top
R168 "CRCW0402365RFKED" 0402L#1 648,1289.66 r270 bottom
R169 "CRCW040222R6FKED" 0402L#1 700.1,1345.84 r180 bottom
R170 "CRCW04021K00FKED" 0402L#1 508.02,1698.53 r90 bottom
R171 "RC0603FR-0762KL" 0603L#1 419.29,1911.52 r0 top
R172 "CRCW060330K1FKEA" 0603L#1 520.99,1911.52 r180 top
R173 "CRCW04021K00FKED" 0402L#1 86.73,1184.99 r90 top
R174 "CRCW0402274KFKED" 0402L#1 64.73,1309.99 r0 top
R175 "CRCW0402100KFKED" 0402L#1 56.73,1253.99 r90 top
R176 "CRCW06035K23FKEA" 0603L#1 574.32,1316 r90 top
R177 "RC0603FR-0795K3L" 0603L#1 623.32,1260.88 r90 top
R178 "CRCW04020000Z0ED" 0402L#1 903.3,1125 r180 bottom
R179 "CRCW04020000Z0ED" 0402L#1 1314.63,1312.84 r0 bottom
R180 "CRCW04020000Z0ED" 0402L#1 1314.63,1347.47 r0 bottom
R181 "CRCW0402100RFKED" 0402L#1 1476,1330.16 r270 bottom
R182 "CRCW04022K00FKED" 0402L#1 1269.78,816 r270 bottom
R183 "CRCW04022K00FKED" 0402L#1 1269.78,738 r90 bottom
Rf+ "CRCW0402127RFKED" 0402L#11 777.93,1364.61 r180 bottom
Rf- "CRCW0402127RFKED" 0402L#11 777.93,1295.71 r180 bottom
Ri+ "CRCW0402365RFKED" 0402L#1 648,1370.65 r90 bottom
Ri- "CRCW040222R6FKED" 0402L#1 700.09,1314.47 r0 bottom
Ro+ "CRCW040240R2FKED" 0402L#1 1004.79,1314.47 r0 bottom
Ro- "CRCW040240R2FKED" 0402L#1 1004.79,1345.84 r0 bottom
RR6 "CRCW06034K99FKEA" 0603L#1 5883.56,2340 r180 top
RR7 "ERJ-3GEY0R00V" 0603L#1 5831,390 r180 top
RSV "TSW-103-07-G-S" TSW-103-07-G-S 1607.28,702 r0 top
S1 "L101011MS02Q" "SW_ L101011MS02Q" 1090,212.6 r270 top
SH-1V2ADC_INT_1_2 "SNT-100-BK-G" SNT-100-BK-G 3842.27,2305 r180 top
SH-1V2ADC_LDO_1_2 "SNT-100-BK-G" SNT-100-BK-G 3535.27,2469 r180 top
SH-1V9ADC_1_2 "SNT-100-BK-G" SNT-100-BK-G 4847,2552.93 r90 top
SH-1V9INT_1_2 "SNT-100-BK-G" SNT-100-BK-G 4796,2319.07 r90 top
SH-5V_12V_1_2 "SNT-100-BK-G" SNT-100-BK-G 5258,90 r180 top
SH-FTDI_3P3V_1_2 "SNT-100-BK-G" SNT-100-BK-G 2229.28,426 r0 top
SH-J2_1_2 "SNT-100-BK-G" SNT-100-BK-G 3294,1415 r180 top
SH-LMK_INT_1_2 "SNT-100-BK-G" SNT-100-BK-G 4207,2040 r180 top
SH-LMK_LDO_1_2 "SNT-100-BK-G" SNT-100-BK-G 3644,2040 r180 top
SH-LMX_INT_1_2 "SNT-100-BK-G" SNT-100-BK-G 4995,2040 r180 top
SH-LMX_LDO_1_2 "SNT-100-BK-G" SNT-100-BK-G 4432,2040 r180 top
SH-RSV_1_2 "969102-0000-DA" SNT-100-BK-G 1557.28,702 r0 top
"SH-Ts ADD1_1_2" "969102-0000-DA" SNT-100-BK-G 2229.28,653 r180 top
SPI "TSW-104-07-G-D" TSW-104-07-G-D 4958,365 r90 top
Status1 "LTST-C190GKT" LED_LTST-C190 2085.5,2274.95 r0 top
Status2 "LTST-C190GKT" LED_LTST-C190 1386.53,2561 r0 top
T2 "TCM2-43X+" Mini-Circuits-DB1627 1030.65,1574.95 r270 bottom
TCRIT1 "TESTPOINT" TESTPOINT#1 2398.28,653 r270 top
TCRIT2 "TESTPOINT" TESTPOINT#1 2501.5,725 r270 top
TCRIT3 "TESTPOINT" TESTPOINT#1 2265.72,937 r270 top
Tdiode "TSW-102-07-G-S" TSW-102-07-G-S 1832.28,777 r270 top
TEMP "LTST-C170KRKT" LED_LTST-C170 2395.28,817.94 r270 top
TMST+ "142-0701-806" Johnson_142-0701-80x 100,1830.16 r270 bottom
TMST- "142-0701-806" Johnson_142-0701-80x 100,2330.16 r270 bottom
"Ts ADD1" "TSW-103-07-G-S" TSW-103-07-G-S 2179.28,653 r180 top
U1 "LMC6762AIMX/NOPB" M08A_L 3399,1140 r270 top
U2 "ADC12J4000NKE" RLY0068A 1725.39,1340 r0 bottom
U3 "LM95233CISD/NOPB" SDA14B 2108.28,796.76 r0 top
U4 "TRF3765IRHB" RHB0032E 2894.24,1790 r270 top
U5 "LP3878MR-ADJ/NOPB" MRA08A_N 3950,2015 r180 top
U6 "LMK04828BISQ/NOPB" NKD0064A 1685.56,2147 r90 top
U7 "TPS54327DDA" DDA0008B_L 5387,1206 r90 top
U8 "LP3878MR-ADJ/NOPB" MRA08A_N 4738,2015 r180 top
U9 "LM26400YSDE/NOPB" SDA16A 4417,1524 r270 top
U10 "TPS74901RGW" RGW0020A 3816.68,2488 r90 top
U11 "LP38513TJ-ADJ/NOPB" TJ5A_N 4379,2436 r180 top
U12 "SN74AVC4T774PW" PW0016A_L 4549,365.53 r0 top
U13 "FT4232HL" LQFP64_N 3397.47,488 r0 top
U14 "TLV70233DBV" DBV0005A_N 228.7,670.86 r180 bottom
U15 "93LC46B-I/MS" MSOP-MS8_N 3462,567 r0 bottom
U16 "24C65T/SM" SOIJ-SM8_N 4770,765 r180 top
U17 "MC10EP32D" 751-06_N 2325.33,1678.5 r180 top
U18 "SN74LVC1G125DBV" SOP-5_.95MM_(DBV) 3426.68,384.9 r90 bottom
U19 "LMH5401IRMSR" RMS0014A 883.61,1330.16 r90 bottom
U20 "TPS79301DBVR" DBV0006A_N 437.99,1810.52 r90 top
U21 "LMR70503TM/NOPB" YFX0008ADAC 121.73,1257.99 r90 top
U22 "TPS72301DBVR" DBV0005A_N 473.32,1316 r0 top
USB "651-305-142-821" CONN_USB-MINI-AB-651-305-142-821 220.47,782.44 r270 top
USB_PWR "LTST-C190GKT" LED_LTST-C190 3042.91,275.2 r270 top
uWIRE "N2510-6002-RB" CONN_2510-6002 4218,440 r90 top
VA12 "TSW-102-07-G-S" TSW-102-07-G-S 3023,2431 r180 top
VA19 "TSW-102-07-G-S" TSW-102-07-G-S 1707.28,927 r90 top
VADJ_RX "5011" Keystone5011 5556,2315 r90 top
Vbg "TSW-102-07-G-S" TSW-102-07-G-S 1544.78,927 r90 top
Vcmo "TSW-103-07-G-S" TSW-103-07-G-S 1369.78,877 r90 top
Vcmo_2_3 "969102-0000-DA" SNT-100-BK-G 1369.78,927 r90 top
VD12 "TSW-102-07-G-S" TSW-102-07-G-S 1985,1078 r180 top
VIN+ "142-0701-231" Johnson_142-0701-231#1 680.41,1633.79 r0 top
VIN- "142-0701-231" Johnson_142-0701-231#2 680.41,1026.53 r0 top
Vtune "TESTPOINT" TESTPOINT#3 3188.24,1513.68 r180 top
Y1 "CWX813-100.0M" OSC_CWX 3391.24,1740 r180 top
Y2 "ABM3-12.000MHZ-B2-T" XTAL_ABM3 3063.47,827 r180 top
ZZ1 "This Assembly Note is for Checking of PCB Box on Top of PCB Lower Left Corner See Table" AssemblyNoteLabel 185,3938 r0 top
ZZ2 "These assemblies are ESD sensitive, ESD precautions shall be observed." AssemblyNote 185,3829.11 r0 top
ZZ3 "These assemblies must be clean and free from flux and all contaminants. Use of no clean flux is not acceptable." AssemblyNote 185,3740.56 r0 top
ZZ4 "These assemblies must comply with workmanship standards IPC-A-610 Class 2., unless otherwise specified." AssemblyNote 185,3652 r0 top

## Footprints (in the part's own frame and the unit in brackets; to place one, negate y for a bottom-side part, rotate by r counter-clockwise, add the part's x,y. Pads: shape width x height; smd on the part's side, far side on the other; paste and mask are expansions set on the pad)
0201#1 [mm] "Data from Kemet datasheet CC101_COM dated 7/28/11"
  rect 0.46x0.42 smd mask+0.048: 1(-0.33,0) 2(0.33,0)
  body extent -0.31,-0.16 0.31,0.16, height 0.26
